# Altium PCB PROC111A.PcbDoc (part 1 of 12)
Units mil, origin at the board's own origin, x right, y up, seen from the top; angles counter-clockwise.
Board outline 7700 x 2300 mil, 6 copper layers (Top Layer, GND 1, SIG 1, SIG 2, GND 2, Bottom Layer), stack 61.062 mil thick; 841 components, 632 nets, 2914 pads, 1627 vias.
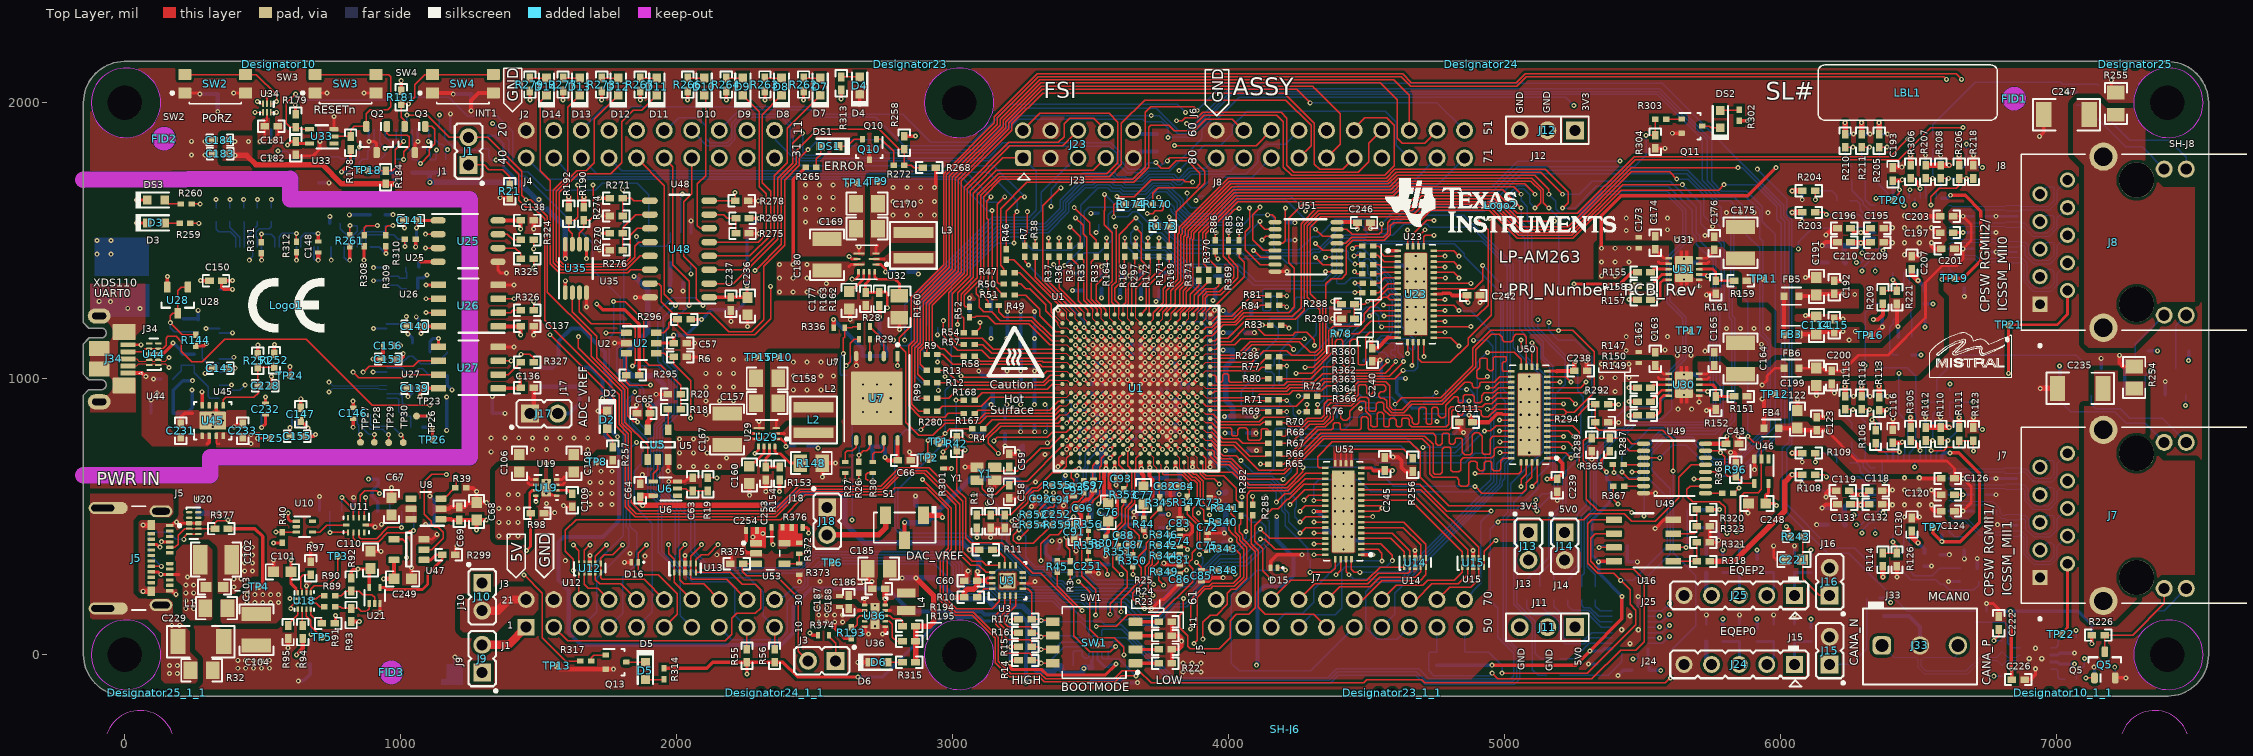
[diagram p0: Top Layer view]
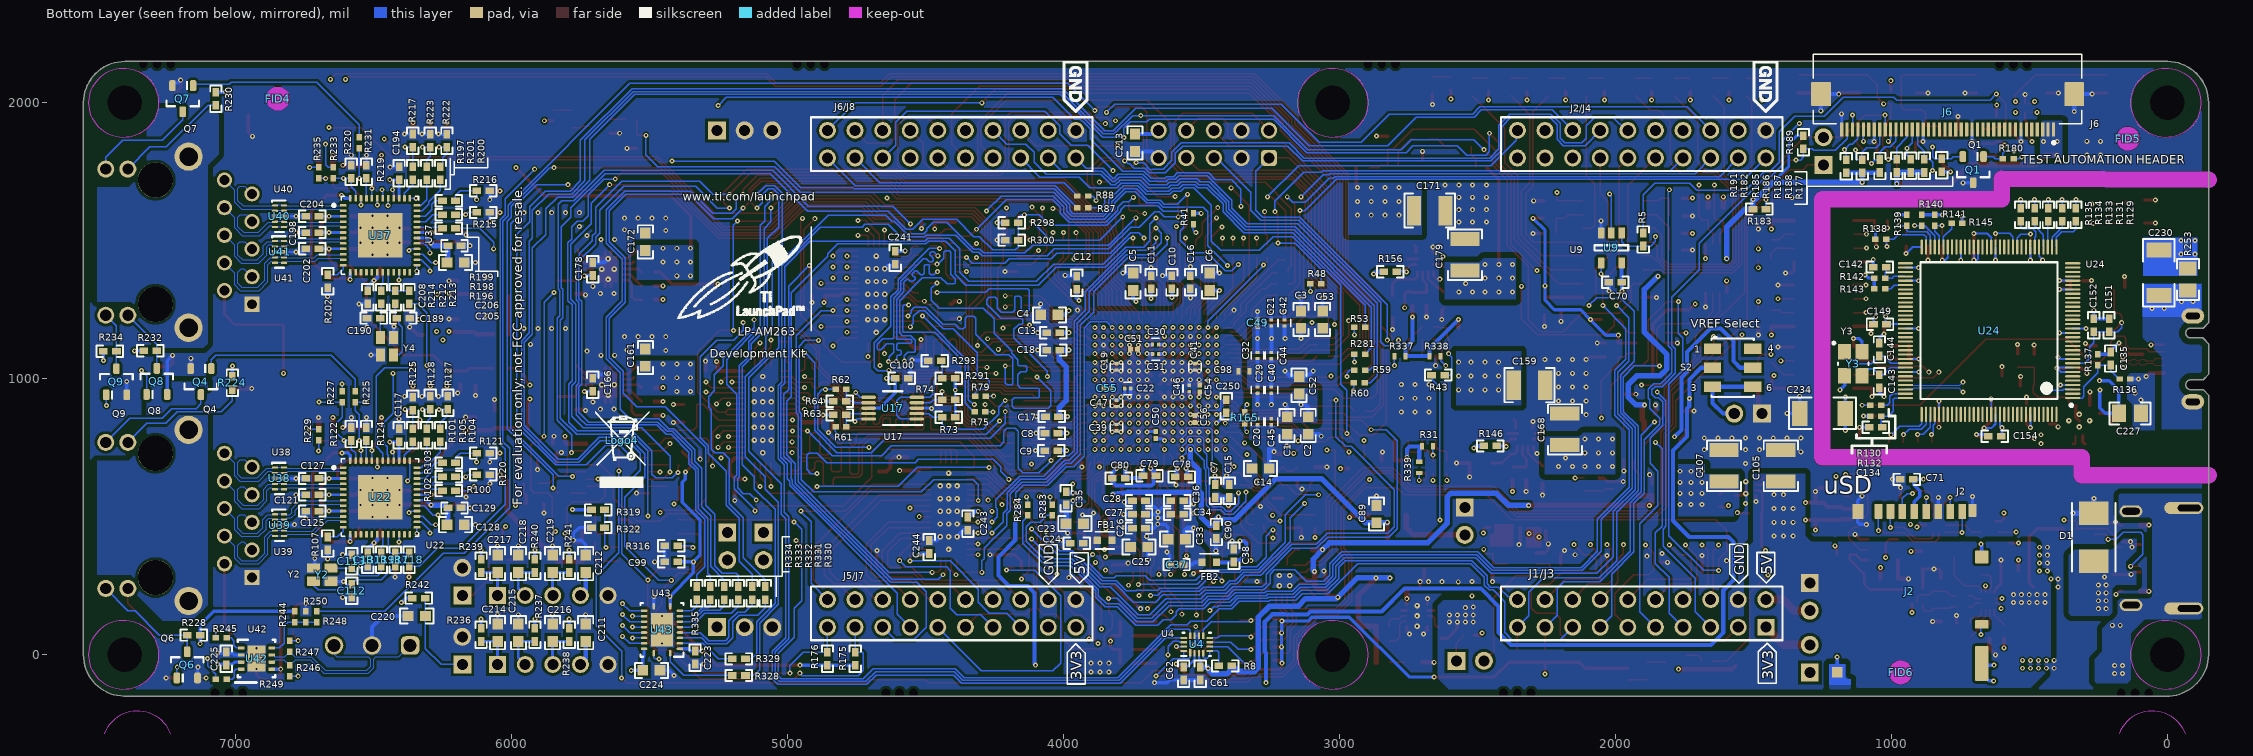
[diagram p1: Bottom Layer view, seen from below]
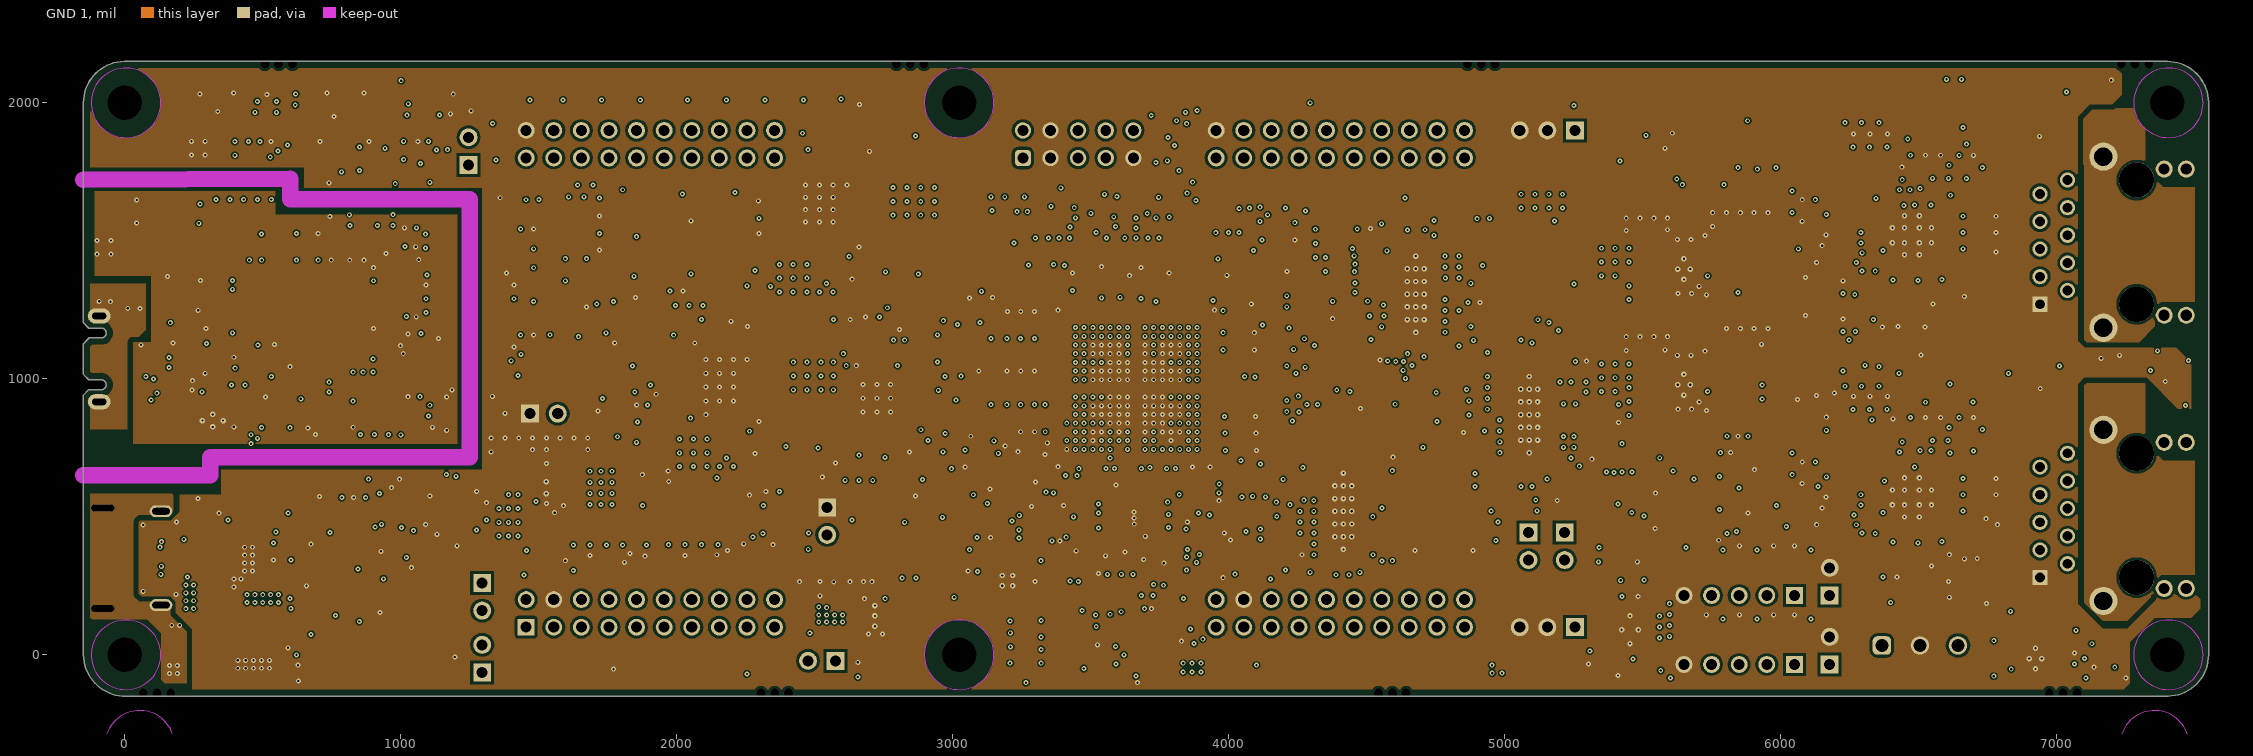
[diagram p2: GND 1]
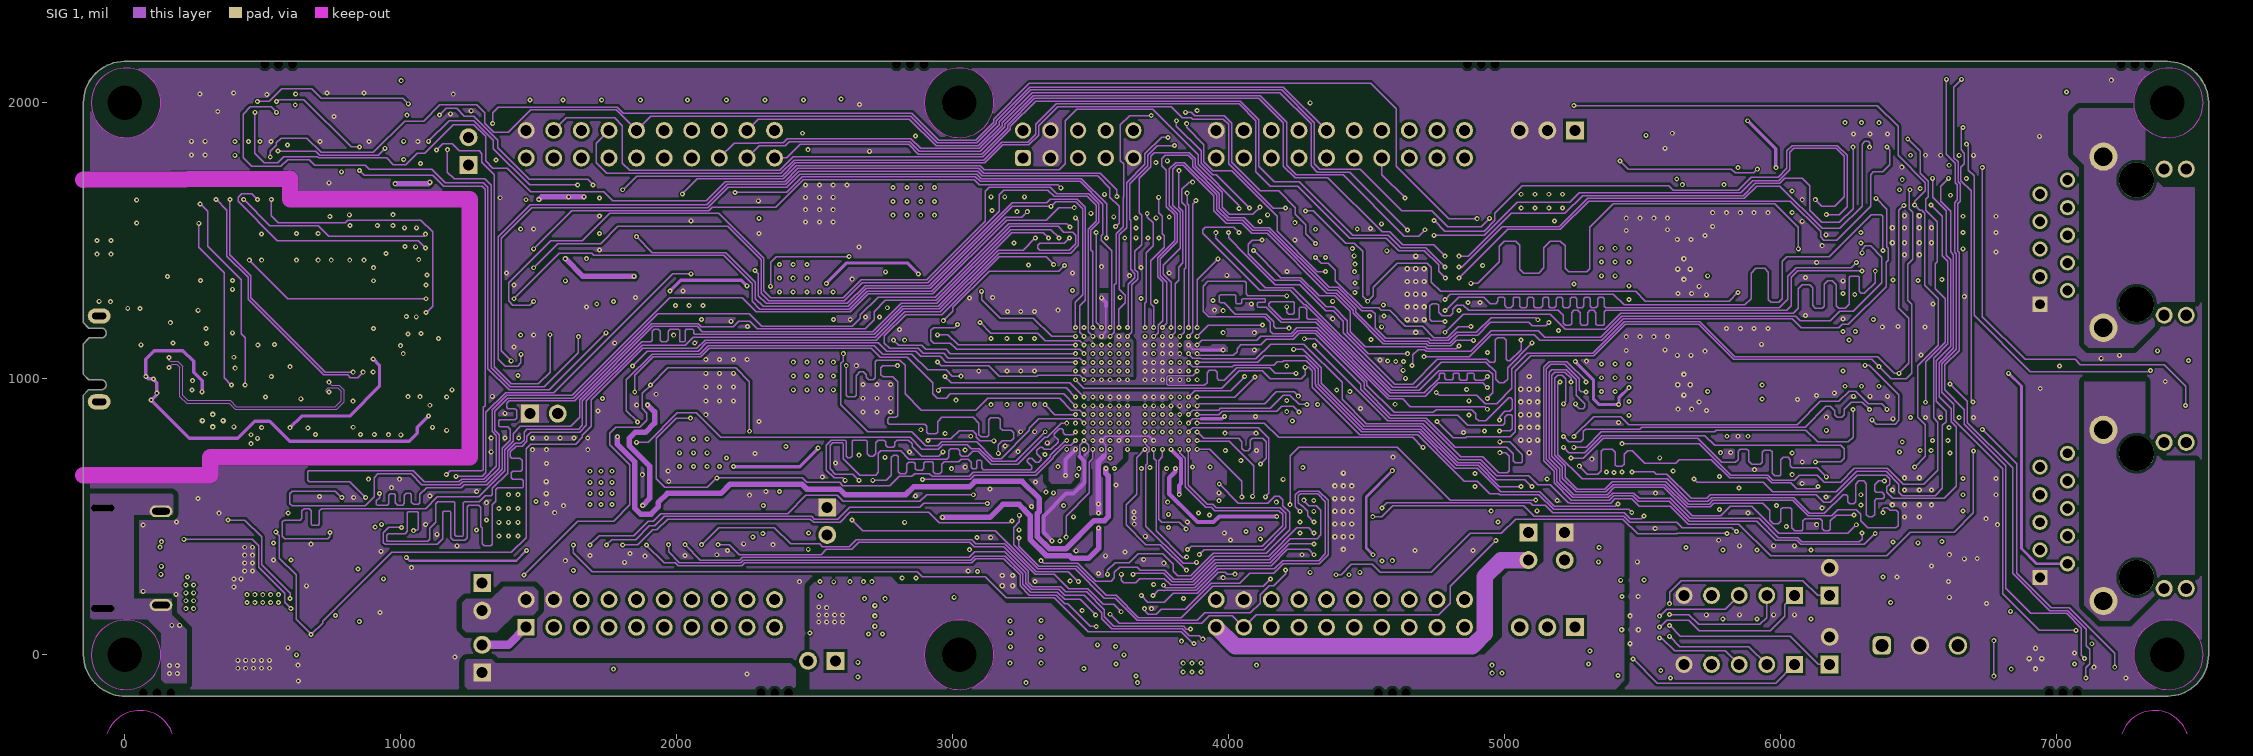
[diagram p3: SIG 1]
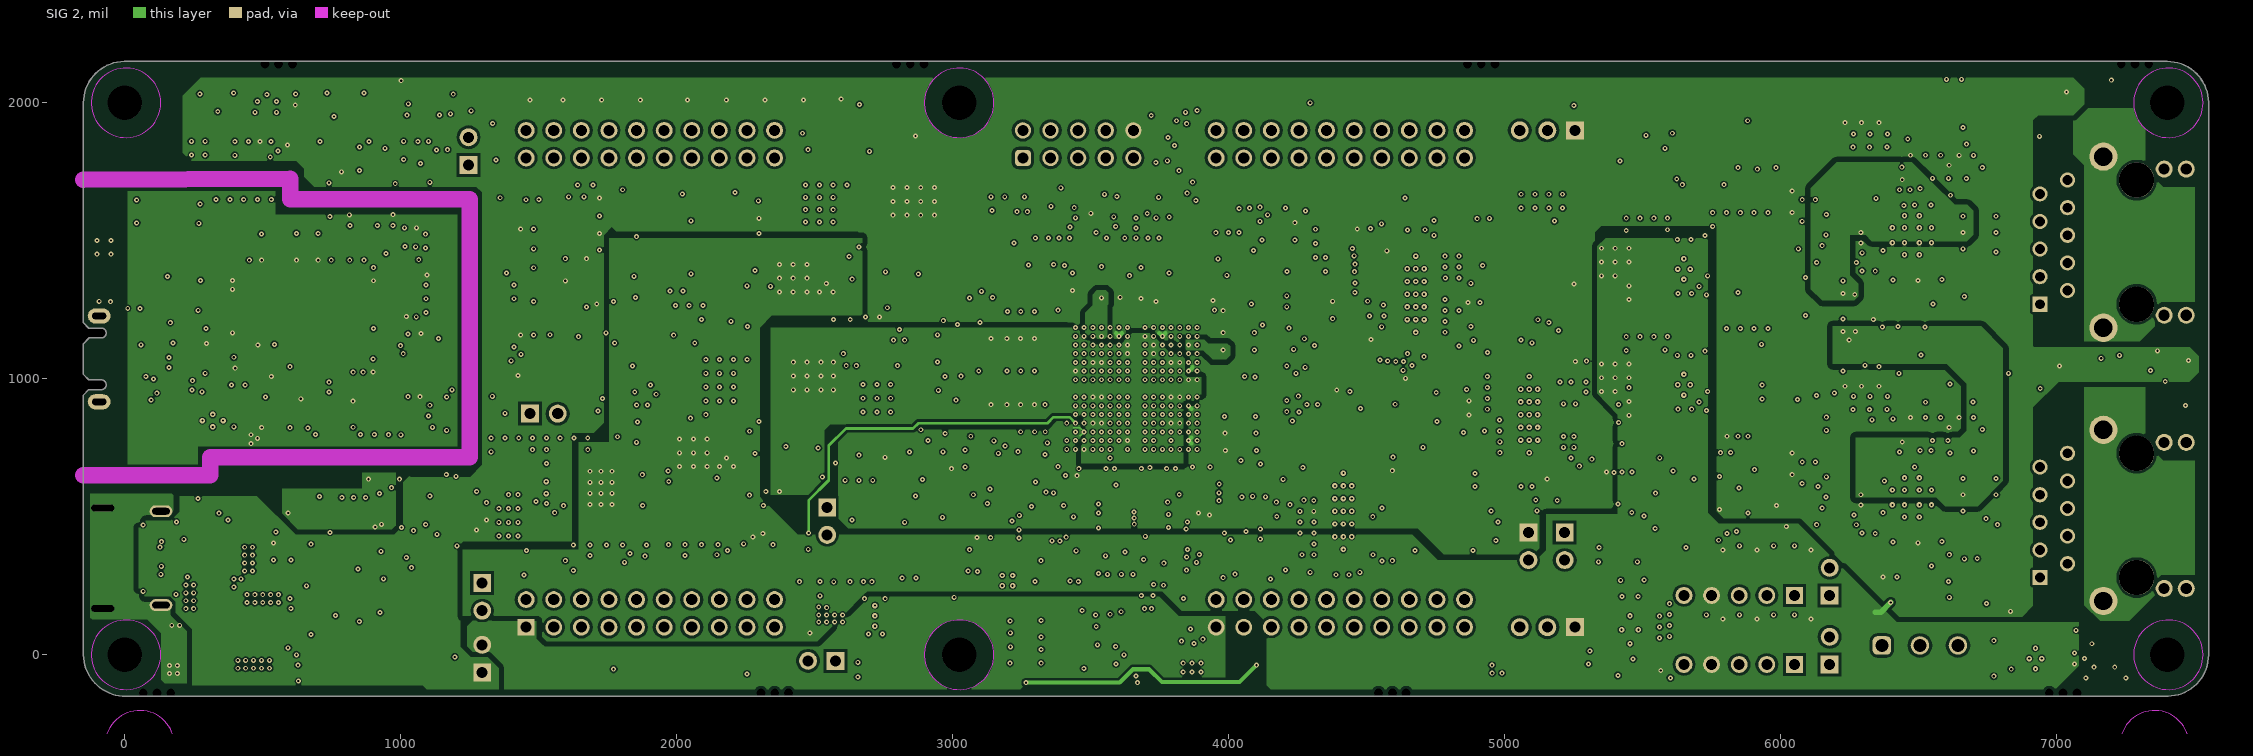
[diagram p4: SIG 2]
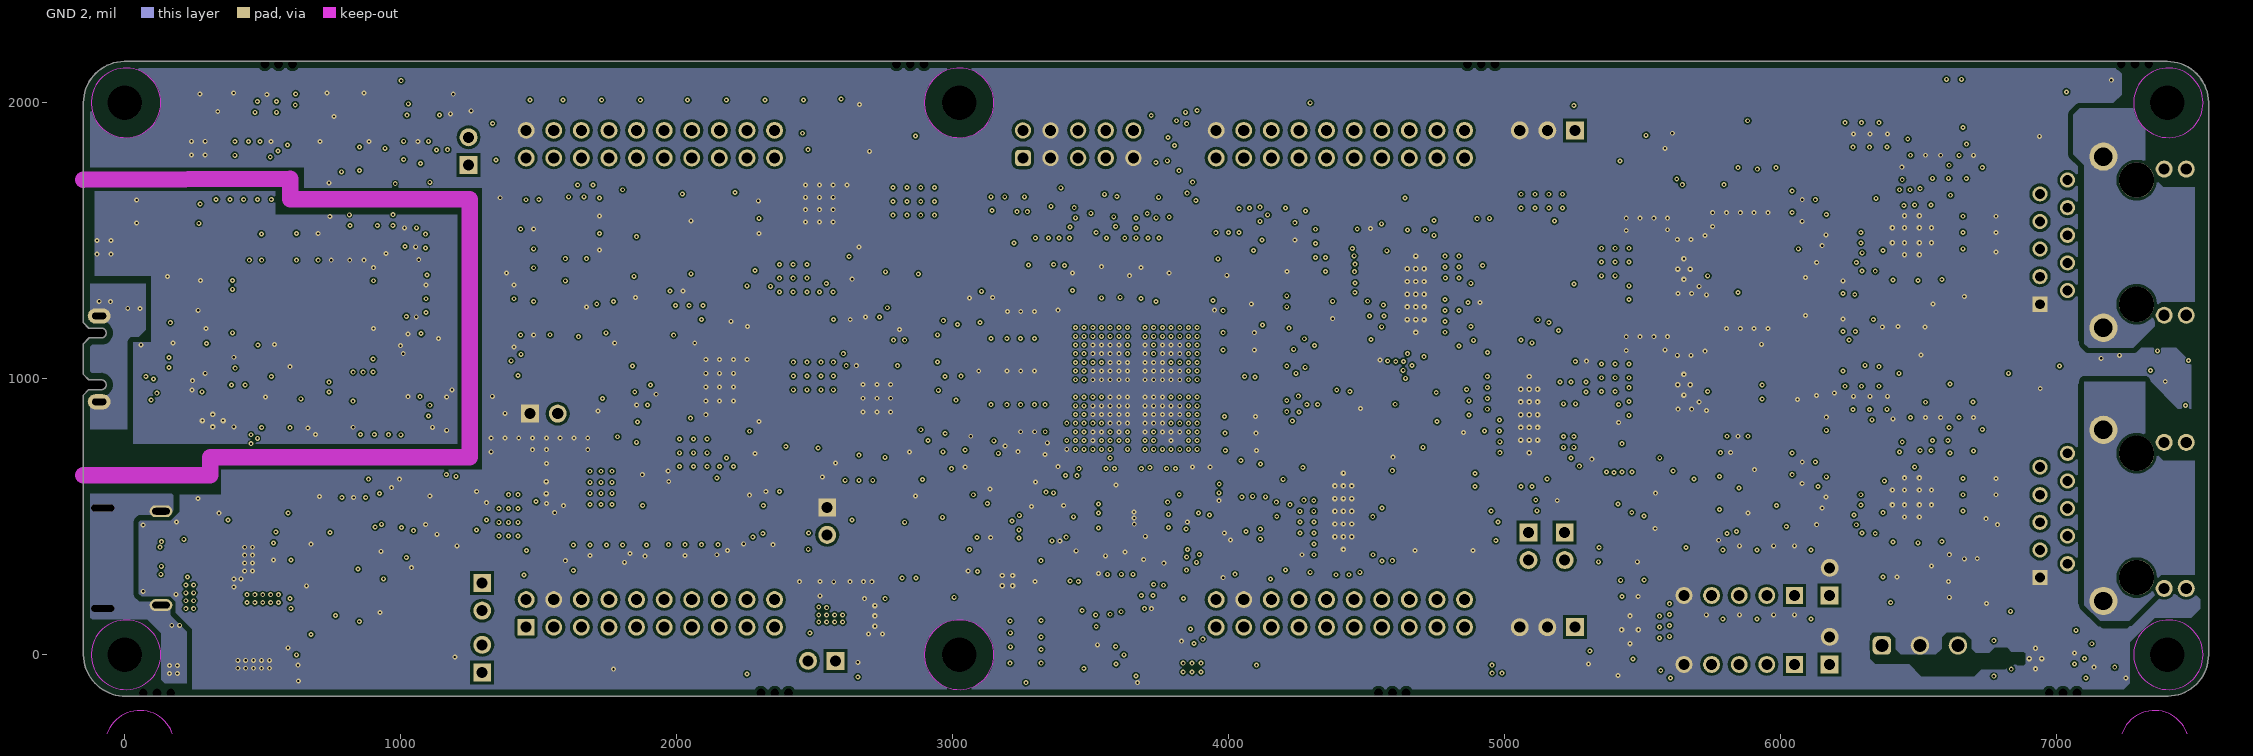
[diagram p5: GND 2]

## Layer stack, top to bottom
Top Solder: solder mask 1, Taiyo PSR 4000 HFX DI-GREEN, Dk 3.5
Top Layer: signal copper 2.087
Dielectric 1: prepreg 3.511, Iteq IT180A Prepreg 2113 RC58, Dk 4.13
GND 1: signal copper 1.26
Dielectric 3: core 4, Iteq IT180A 4 mil core 1/1, Dk 4.4
SIG 1: signal copper 1.26
Dielectric 5: core 1.75, Iteq IT180A Prepreg 106 RC71.5, Dk 3.79
Dielectric 7: core 2.663, Iteq IT180A Prepreg 1080 RC65, Dk 3.86
Dielectric1: core 28, Iteq IT180A 28 mil core H/H, Dk 4.53
Dielectric 8: core 2.663, Iteq IT180A Prepreg 1080 RC65, Dk 3.86
Dielectric 6: core 1.75, Iteq IT180A Prepreg 106 RC71.5, Dk 3.79
SIG 2: signal copper 1.26
Dielectric 4: core 4, Iteq IT180A 4 mil core 1/1, Dk 4.4
GND 2: signal copper 1.26
Dielectric 2: prepreg 3.511, Iteq IT180A Prepreg 2113 RC58, Dk 4.13
Bottom Layer: signal copper 2.087
Bottom Solder: solder mask 1, Taiyo PSR 4000 HFX DI-GREEN, Dk 3.5

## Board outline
-150,0 -150,941.28 -130.32,960.97 -84.25,960.97 ccw(c-84.25,977.87) -67.34,977.87 ccw(c-85.87,977.87) -85.87,996.4 -130.32,996.4 -150,1016.08 -150,1127.3 -130.32,1146.99 -130.32,1147.97 -85.04,1147.97 ccw(c-85.04,1165.67) -67.34,1165.67 -67.34,1166.5 ccw(c-84.25,1166.5) -84.25,1183.41 -130.32,1183.41 -150,1203.09 -150,1278.88 -150,1999.99 cw(c0,2000) -2.06,2149.99 0,2150 7399.99,2150 cw(c7400,2000) 7549.99,2002.06 7550,2000 7550,0.01 cw(c7400,0) 7402.06,-149.99 7400,-149.99 0,-150 4.17,-150 cw(c2.09,2.09)

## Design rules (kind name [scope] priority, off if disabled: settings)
AssemblyTestPointUsage [All] p1: valid=2
BoardOutlineClearance BoardOutlineClearance_MountingHoles [OnCopper and InComponentClass('Mounting Holes')] p1: gap=39.37 ignorepadtopadclearanceinfootprint=FALSE
BoardOutlineClearance BoardOutlineClearance_Poly [OnCopper and IsPoly] p2: gap=25 ignorepadtopadclearanceinfootprint=FALSE
BoardOutlineClearance [OnCopper and Not InComponentClass('Logo') and not InComponentClass('FiducialMark') and not InRegion(1000,500,4000,800) and not InPoly] p3: gap=40 ignorepadtopadclearanceinfootprint=FALSE except(15: SMDPad-OutlineEdge THPad-OutlineEdge; 25: Fill-OutlineEdge)
Clearance Clearance_Keepouts [IsKeepOut] p1: gap=1 ignorepadtopadclearanceinfootprint=FALSE
Clearance proc111 [WithinRoom('PROC111_Hardware')] p2: gap=4 ignorepadtopadclearanceinfootprint=TRUE except(8: Fill-Fill Fill-Poly Fill-Region; 12: Poly-Poly Poly-Region Region-Region)
Clearance 4mil [WithinRoom('SOC_4mil')] p3: gap=4 ignorepadtopadclearanceinfootprint=TRUE except(15: Fill-Fill Fill-Poly Fill-Region Poly-Poly Poly-Region Region-Region)
Clearance ADC_EXT [(OnLayer('Top Layer') or OnLayer('Bottom Layer')) vs InNetClass('ADC0')] p4: gap=7.87 ignorepadtopadclearanceinfootprint=TRUE except(6: Via-Fill Via-Poly Via-Region; 10.6: Arc-Arc Arc-Track Track-Track; 18: Via-Via; 25: Fill-Fill Fill-Poly Fill-Region Poly-Poly Poly-Region Region-Region)
Clearance ADC_SIG1 [OnLayer('SIG 1') vs InNetClass('ADC0')] p5: gap=7.87 ignorepadtopadclearanceinfootprint=TRUE except(6: Via-Fill Via-Poly Via-Region; 9.5: Arc-Arc Arc-Track Track-Track; 18: Via-Via; 25: Fill-Fill Fill-Poly Fill-Region Poly-Poly Poly-Region Region-Region)
Clearance 100E_CLR_same [InDifferentialPairClass('100E')] p6: gap=7.87 ignorepadtopadclearanceinfootprint=TRUE except(7.7: Arc-Arc Arc-Track Track-Track; 10: Via-Fill Via-Poly Via-Region; 18: Via-Via; 25: Fill-Fill Fill-Poly Fill-Region Poly-Poly Poly-Region Region-Region)
Clearance 100E_CLR [InDifferentialPairClass('100E')] p7: gap=7.87 ignorepadtopadclearanceinfootprint=TRUE except(6: Via-Fill Via-Poly Via-Region; 16.2: Arc-Arc Arc-Track Track-Track; 18: Via-Via; 25: Fill-Fill Fill-Poly Fill-Region Poly-Poly Poly-Region Region-Region)
Clearance Clearance_Poly [InPolygon] p8: gap=10 ignorepadtopadclearanceinfootprint=TRUE except(4: Via-Fill Via-Poly Via-Region; 20: Fill-Fill Fill-Poly Fill-Region Poly-Poly Poly-Region Region-Region)
Clearance DIff_spacing [All vs InDifferentialPair('XDSET_1_D')] p9: gap=7.87 ignorepadtopadclearanceinfootprint=TRUE except(5: Arc-Arc Arc-Track Track-Track; 6: Via-Fill Via-Poly Via-Region; 18: Via-Via; 25: Fill-Fill Fill-Poly Fill-Region Poly-Poly Poly-Region Region-Region)
Clearance [All] p10: gap=7.87 ignorepadtopadclearanceinfootprint=TRUE except(5.3: Arc-Arc Arc-Track Track-Track; 6: SMDPad-SMDPad Via-Fill Via-Poly Via-Region; 7: Via-Via; 7.4: Arc-SMDPad Track-SMDPad; 7.5: SMDPad-Via; 25: Fill-Fill Fill-Poly Fill-Region Poly-Poly Poly-Region Region-Region)
ComponentClearance ComponentClearance_EXCEPTION [HasFootprint('0402_070*')or HasFootprint('0402*')] p1: gap=8 collisioncheckmode=3 verticalgap=8 showdistances=FALSE
ComponentClearance ComponentClearance_MountingHoles_FiducialMarks [InComponentClass('Mounting Holes') vs InComponentClass('FiducialMark')] p2: gap=50 collisioncheckmode=3 verticalgap=10 showdistances=FALSE
ComponentClearance ComponentClearance_Shunt [InComponentClass('Header') vs InComponentClass('Shunt')] p3: gap=0 collisioncheckmode=3 verticalgap=0 showdistances=FALSE
ComponentClearance ComponentClearance_Logo [InComponentClass('Logo')] p4: gap=30 collisioncheckmode=3 verticalgap=10 showdistances=FALSE
ComponentClearance ComponentClearance_ScrewToNut [(HasFootprint('NY PMS 440 0025 PH')) vs (HasFootprint('Keystone_1902C'))] p5: gap=5 collisioncheckmode=3 verticalgap=10 showdistances=FALSE
ComponentClearance ComponentClearance_MountingHoles [InComponentClass('Mounting Holes')] p6: gap=100 collisioncheckmode=3 verticalgap=100000 showdistances=FALSE
ComponentClearance ComponentClearance_SmallPassives [HasFootprint('0201*') or HasFootprint('0508') or HasFootprint('0603*') or HasFootprint('0612') or HasFootprint('0805*') or HasFootprint('0815*') or HasFootprint('0830*') or HasFootprint('1206*') or HasFootprint('1210*') or HasFootprint('1808*') or HasFootprint('1812*') or HasFootprint('1825*') or HasFootprint('2010*') or HasFootprint('2220*') or HasFootprint('2225*') or HasFootprint('2512*') or HasFootprint('2728*') or HasFootprint('3518*') vs HasFootprint('0201*') or HasFootprint('0402*') or HasFootprint('0508') or HasFootprint('0603*') or HasFootprint('0612') or HasFootprint('0805*') or HasFootprint('0815*') or HasFootprint('0830*') or HasFootprint('1206*') or HasFootprint('1210*') or HasFootprint('1808*') or HasFootprint('1812*') or HasFootprint('1825*') or HasFootprint('2010*') or HasFootprint('2220*') or HasFootprint('2225*') or HasFootprint('2512*') or HasFootprint('2728*') or HasFootprint('3518*')] p7: gap=10 collisioncheckmode=3 verticalgap=10 showdistances=FALSE
ComponentClearance ComponentClearance_THtoSMT [IsThruComponent vs IsSMTComponent] p8: gap=30 collisioncheckmode=3 verticalgap=30 showdistances=FALSE
ComponentClearance ComponentClearance_THtoTH [IsThruComponent vs IsThruComponent] p9: gap=20 collisioncheckmode=3 verticalgap=30 showdistances=FALSE
ComponentClearance [All] p10: gap=15 collisioncheckmode=3 verticalgap=15 showdistances=TRUE
DiffPairsRouting 90E [InDifferentialPair('XDSET_1_D')] p1: maxlimit=10 minlimit=5 mostfreqgap=10 toplayer_prefgap=5 toplayer_minwidth=4.2 toplayer_maxwidth=15 toplayer_prefwidth=4.2 midlayer1_mingap=6 midlayer1_maxgap=6 midlayer1_prefgap=6 midlayer1_minwidth=4 midlayer1_maxwidth=4 midlayer1_prefwidth=4 midlayer2_mingap=10 midlayer2_minwidth=15 midlayer2_maxwidth=15 midlayer2_prefwidth=15 midlayer3_mingap=10 midlayer3_minwidth=15 midlayer3_maxwidth=15 midlayer3_prefwidth=15 midlayer4_mingap=10 midlayer4_minwidth=15 midlayer4_maxwidth=15 midlayer4_prefwidth=15 bottomlayer_prefgap=5 bottomlayer_minwidth=4.2 bottomlayer_maxwidth=15 bottomlayer_prefwidth=4.2 maxuncoupledlength=500
DiffPairsRouting 120E [InDifferentialPair('CANA')] p2: maxlimit=10 minlimit=6.8 mostfreqgap=10 toplayer_prefgap=6.8 toplayer_minwidth=4.1 toplayer_maxwidth=15 toplayer_prefwidth=4.1 midlayer1_mingap=10 midlayer1_minwidth=15 midlayer1_maxwidth=15 midlayer1_prefwidth=15 midlayer2_mingap=10 midlayer2_minwidth=15 midlayer2_maxwidth=15 midlayer2_prefwidth=15 midlayer3_mingap=10 midlayer3_minwidth=15 midlayer3_maxwidth=15 midlayer3_prefwidth=15 midlayer4_mingap=10 midlayer4_minwidth=15 midlayer4_maxwidth=15 midlayer4_prefwidth=15 bottomlayer_prefgap=6.8 bottomlayer_minwidth=4.1 bottomlayer_maxwidth=15 bottomlayer_prefwidth=4.1 maxuncoupledlength=500
DiffPairsRouting 100E_DIFF [InDifferentialPairClass('100E')] p3: maxlimit=100 minlimit=7.7 mostfreqgap=10 toplayer_maxgap=7.7 toplayer_prefgap=7.7 toplayer_minwidth=4 toplayer_maxwidth=4 toplayer_prefwidth=4 midlayer1_mingap=8.1 midlayer1_maxgap=8.1 midlayer1_prefgap=8.1 midlayer1_minwidth=3.5 midlayer1_maxwidth=3.5 midlayer1_prefwidth=3.5 midlayer2_mingap=10 midlayer2_minwidth=15 midlayer2_maxwidth=15 midlayer2_prefwidth=15 midlayer3_mingap=10 midlayer3_minwidth=15 midlayer3_maxwidth=15 midlayer3_prefwidth=15 midlayer4_mingap=10 midlayer4_minwidth=15 midlayer4_maxwidth=15 midlayer4_prefwidth=15 bottomlayer_maxgap=7.7 bottomlayer_prefgap=7.7 bottomlayer_minwidth=4 bottomlayer_maxwidth=4 bottomlayer_prefwidth=4 maxuncoupledlength=1000
FabricationTestPointUsage TestPointUsage [All] p1: valid=2 allowmultiple=FALSE
FabricationTestpoint Testpoint [All] p1: side=3 testpointundercomponent=TRUE minsize=40 maxsize=100 preferedsize=60 minholesize=0 maxholesize=40 preferedholesize=32 testpointgrid=1 allowsidetop=TRUE allowsidebottom=TRUE usegrid=TRUE gridtolerance=0.01
FanoutControl Fanout_LCC [IsLCC] p1: bgadir=Out bgaviamode=Centered fanoutstyle=Auto fanoutdirection=Alternating viagrid=1 // Fanout_LCC (Default Rule)
FanoutControl Fanout_BGA [IsBGA] p2: bgadir=Out bgaviamode=Centered fanoutstyle=Auto fanoutdirection=Alternating viagrid=1 // Fanout_BGA (Default Rule)
FanoutControl Fanout_Default [All] p4: bgadir=Out bgaviamode=Centered fanoutstyle=Auto fanoutdirection=Alternating viagrid=1 // Fanout_Default (Default Rule)
FanoutControl Fanout_Small [(CompPinCount < 5)] p5: bgadir=Out bgaviamode=Centered fanoutstyle=Auto fanoutdirection=OutThenIn viagrid=1 // Fanout_Small (Default Rule)
HoleSize [All] p1: absolutevalues=TRUE maxlimit=251 minlimit=7.87 maxpercent=80.000 minpercent=20.000
MatchedLengths DIFF [All] p1: tolerance=2 checknetsindiffpair=TRUE checkdiffpairvsdiffpair=FALSE checkxsignals=FALSE checkothers=FALSE
MatchedLengths QSPI [InxSignalClass('QSPI_FLASH')] p2: tolerance=25 checknetsindiffpair=FALSE checkdiffpairvsdiffpair=TRUE checkxsignals=TRUE checkothers=TRUE
MatchedLengths ETH1_RX [InxSignalClass('ETH1_RX')] p3: tolerance=7.5 checknetsindiffpair=FALSE checkdiffpairvsdiffpair=TRUE checkxsignals=TRUE checkothers=TRUE
MatchedLengths ETH1_TX [InxSignalClass('ETH1_TX')] p4: tolerance=7.5 checknetsindiffpair=FALSE checkdiffpairvsdiffpair=TRUE checkxsignals=TRUE checkothers=TRUE
MatchedLengths ICSSM_MII0_RX [InxSignalClass('ICSSM_MII0_RX')] p5: tolerance=7.5 checknetsindiffpair=FALSE checkdiffpairvsdiffpair=TRUE checkxsignals=TRUE checkothers=TRUE
MatchedLengths AM263_RGMII1_TX [InxSignalClass('AM263_RGMII1_TX')] p6: tolerance=7.5 checknetsindiffpair=FALSE checkdiffpairvsdiffpair=TRUE checkxsignals=TRUE checkothers=TRUE
MatchedLengths PRO_PROU_GPIO(0-6) [InxSignalClass('PRO_PROU_GPIO(0-6)')] p7: tolerance=7.5 checknetsindiffpair=FALSE checkdiffpairvsdiffpair=TRUE checkxsignals=TRUE checkothers=TRUE
MatchedLengths PRO_PROU_GPIO(11-16) [InxSignalClass('PRO_PROU_GPIO(11-16)')] p8: tolerance=7.5 checknetsindiffpair=FALSE checkdiffpairvsdiffpair=TRUE checkxsignals=TRUE checkothers=TRUE
MatchedLengths AM263_RGMII1_RX [InxSignalClass('AM263_RGMII1_RX')] p9: tolerance=7.5 checknetsindiffpair=FALSE checkdiffpairvsdiffpair=TRUE checkxsignals=TRUE checkothers=TRUE
MatchedLengths ICSSM_MII0_TX [InxSignalClass('ICSSM_MII0_TX')] p10: tolerance=7.5 checknetsindiffpair=FALSE checkdiffpairvsdiffpair=TRUE checkxsignals=TRUE checkothers=TRUE
MatchedLengths ICSSM_MII1_TX [InxSignalClass('ICSSM_MII1_TX')] p11: tolerance=7.5 checknetsindiffpair=FALSE checkdiffpairvsdiffpair=TRUE checkxsignals=TRUE checkothers=TRUE
MatchedLengths ICSSM_MII1_RX [InxSignalClass('ICSSM_MII1_RX')] p12: tolerance=7.5 checknetsindiffpair=FALSE checkdiffpairvsdiffpair=TRUE checkxsignals=TRUE checkothers=TRUE
MatchedLengths "SD CARD" [InxSignalClass('MMC0')] p13: tolerance=25 checknetsindiffpair=FALSE checkdiffpairvsdiffpair=TRUE checkxsignals=TRUE checkothers=TRUE
MinimumAnnularRing MinimumAnnularRing_ThermalPadVias [IsVia and InAnyComponent] p1: minimumring=5.91
MinimumAnnularRing [All] p2: minimumring=5
MinimumSolderMaskSliver MinimumSolderMaskSliver_Logo [InComponentClass('Logo') vs InComponentClass('Logo')] p1: minsoldermaskwidth=0.7
PlaneConnect [All] p1: planeconnectstyle=Direct reliefexpansion=10 reliefentries=4 reliefconductorwidth=10 reliefairgap=10
PolygonConnect PolygonConnect_3 [All vs IsNamedPolygon('SIG 2-vusb_3v3')] p1: connectstyle=Direct reliefconductorwidth=10 reliefentries=4 polygonreliefangle="90 Angle" airgapwidth=10
PolygonConnect PolygonConnect_2 [All vs IsNamedPolygon('Top Layer-VBUS_TYPEC_5V0')] p2: connectstyle=Direct reliefconductorwidth=10 reliefentries=4 polygonreliefangle="90 Angle" airgapwidth=10
PolygonConnect PolygonConnect_1 [All vs IsNamedPolygon('Top Layer-VBUS_TYPEC_5V0')] p3: connectstyle=Direct reliefconductorwidth=10 reliefentries=4 polygonreliefangle="90 Angle" airgapwidth=10
PolygonConnect [All] p4: connectstyle=Direct reliefconductorwidth=10 reliefentries=4 polygonreliefangle="90 Angle" airgapwidth=10
RoomDefinition PROC111_AM263x_1_Power [InComponentClass('PROC111_AM263x_1_Power')] p1: confinementstyle=ConfineIn formatcopy=TRUE lockcomponents=FALSE outline -842,-1684 1158,-1684 1158,-684 -842,-684
RoomDefinition PROC111_AM263x_8_SDFM [InComponentClass('PROC111_AM263x_8_SDFM')] p2: confinementstyle=ConfineIn formatcopy=TRUE lockcomponents=FALSE outline 7608,966 8433,966 8433,1166 7608,1166
RoomDefinition PROC111_XDS110_2 [InComponentClass('PROC111_XDS110_2')] p3: confinementstyle=ConfineIn formatcopy=TRUE lockcomponents=FALSE outline -842,-1684 1158,-1684 1158,-684 -842,-684
RoomDefinition PROC111_XDS110_1 [InComponentClass('PROC111_XDS110_1')] p4: confinementstyle=ConfineIn formatcopy=TRUE lockcomponents=FALSE outline -842,-1684 1158,-1684 1158,-684 -842,-684
RoomDefinition PROC111_Test_Automation [InComponentClass('PROC111_Test_Automation')] p5: confinementstyle=ConfineIn formatcopy=TRUE lockcomponents=FALSE outline -842,-1684 1158,-1684 1158,-684 -842,-684
RoomDefinition PROC111_System_Power_2 [InComponentClass('PROC111_System_Power_2')] p6: confinementstyle=ConfineIn formatcopy=TRUE lockcomponents=FALSE outline -842,-1684 1158,-1684 1158,-684 -842,-684
RoomDefinition PROC111_System_Power_1 [InComponentClass('PROC111_System_Power_1')] p7: confinementstyle=ConfineIn formatcopy=TRUE lockcomponents=FALSE outline -842,-1684 1158,-1684 1158,-684 -842,-684
RoomDefinition PROC111_Push_Buttons [InComponentClass('PROC111_Push_Buttons')] p8: confinementstyle=ConfineIn formatcopy=TRUE lockcomponents=FALSE outline -842,-1684 1158,-1684 1158,-684 -842,-684
RoomDefinition PROC111_LED [InComponentClass('PROC111_LED')] p9: confinementstyle=ConfineIn formatcopy=TRUE lockcomponents=FALSE outline -842,-1684 1158,-1684 1158,-684 -842,-684
RoomDefinition PROC111_Ehernet_RJ45_2 [InComponentClass('PROC111_Ehernet_RJ45_2')] p10: confinementstyle=ConfineIn formatcopy=TRUE lockcomponents=FALSE outline -842,-1684 1158,-1684 1158,-684 -842,-684
RoomDefinition PROC111_Ehernet_RJ45_1 [InComponentClass('PROC111_Ehernet_RJ45_1')] p11: confinementstyle=ConfineIn formatcopy=TRUE lockcomponents=FALSE outline -842,-1684 1158,-1684 1158,-684 -842,-684
RoomDefinition PROC111_Ehernet_PHY_2 [InComponentClass('PROC111_Ehernet_PHY_2')] p12: confinementstyle=ConfineIn formatcopy=TRUE lockcomponents=FALSE outline -842,-1684 1158,-1684 1158,-684 -842,-684
RoomDefinition PROC111_Ehernet_PHY_1 [InComponentClass('PROC111_Ehernet_PHY_1')] p13: confinementstyle=ConfineIn formatcopy=TRUE lockcomponents=FALSE outline -842,-1684 1158,-1684 1158,-684 -842,-684
RoomDefinition PROC111_Breakout_Headers [InComponentClass('PROC111_Breakout_Headers')] p14: confinementstyle=ConfineIn formatcopy=TRUE lockcomponents=FALSE outline -842,-1684 1158,-1684 1158,-684 -842,-684
RoomDefinition PROC111_Boosterpack_Headers [InComponentClass('PROC111_Boosterpack_Headers')] p15: confinementstyle=ConfineIn formatcopy=TRUE lockcomponents=FALSE outline -842,-1684 1158,-1684 1158,-684 -842,-684
RoomDefinition PROC111_AM263x_Serial_Connectivity [InComponentClass('PROC111_AM263x_Serial_Connectivity')] p16: confinementstyle=ConfineIn formatcopy=TRUE lockcomponents=FALSE outline -842,-1684 1158,-1684 1158,-684 -842,-684
RoomDefinition PROC111_AM263x_7_PRU [InComponentClass('PROC111_AM263x_7_PRU')] p17: confinementstyle=ConfineIn formatcopy=TRUE lockcomponents=FALSE outline -842,-1684 1158,-1684 1158,-684 -842,-684
RoomDefinition PROC111_AM263x_6_RGMII_MII [InComponentClass('PROC111_AM263x_6_RGMII_MII')] p18: confinementstyle=ConfineIn formatcopy=TRUE lockcomponents=FALSE outline -842,-1684 1158,-1684 1158,-684 -842,-684
RoomDefinition PROC111_AM263x_5_ePWM_eQEP_FSI [InComponentClass('PROC111_AM263x_5_ePWM_eQEP_FSI')] p19: confinementstyle=ConfineIn formatcopy=TRUE lockcomponents=FALSE outline -842,-1684 1158,-1684 1158,-684 -842,-684
RoomDefinition PROC111_AM263x_4_ADC_DAC [InComponentClass('PROC111_AM263x_4_ADC_DAC')] p20: confinementstyle=ConfineIn formatcopy=TRUE lockcomponents=FALSE outline -842,-1684 1158,-1684 1158,-684 -842,-684
RoomDefinition PROC111_AM263x_3_QSPI_MMC [InComponentClass('PROC111_AM263x_3_QSPI_MMC')] p21: confinementstyle=ConfineIn formatcopy=TRUE lockcomponents=FALSE outline -842,-1684 1158,-1684 1158,-684 -842,-684
RoomDefinition PROC111_AM263x_2_Clock_Reset_Boot_JTAG [InComponentClass('PROC111_AM263x_2_Clock_Reset_Boot_JTAG')] p22: confinementstyle=ConfineIn formatcopy=TRUE lockcomponents=FALSE outline -842,-1684 1158,-1684 1158,-684 -842,-684
RoomDefinition PROC111_Hardware [InComponentClass('PROC111_Hardware')] p23: confinementstyle=ConfineIn formatcopy=TRUE lockcomponents=FALSE outline 3365.64,665.87 3964.06,665.87 3964.06,1264.29 3365.64,1264.29
RoutingLayers [All] p1: top layer_v5=TRUE mid layer 1_v5=TRUE mid layer 2_v5=TRUE mid layer 3_v5=FALSE mid layer 4_v5=TRUE bottom layer_v5=TRUE
RoutingVias ThermalPadVias [IsVia and InAnyComponent] p1: holewidth=7.87 width=19.68 viastyle="Through Hole" minholewidth=7.87 minwidth=19.68 maxholewidth=12.99 maxwidth=23.62
RoutingVias [All] p2: holewidth=8 width=18 viastyle="Through Hole" minholewidth=8 minwidth=18 maxholewidth=8 maxwidth=18
SilkToBoardRegionClearance [Not ((IsComment or IsDesignator) And (Hide <> 'False')) and not InRegion(1000,500,4000,800)] p1:
SilkToSilkClearance SilkToSilkClearance_Pb-FreeLogo [(HasFootprint('Pb-Free_Overlay_Medium') OR HasFootprint('Pb-Free_Overlay_Small')) vs (HasFootprint('Pb-Free_Overlay_Medium') OR HasFootprint('Pb-Free_Overlay_Small'))] p1: silktosilkclearance=0
SilkToSilkClearance [All] p2: silktosilkclearance=3.94
SilkToSolderMaskClearance SilkToComponentPadClearance [(IsPad or IsFill or IsRegion) and Component] p1: minsilkscreentomaskgap=3.54 clearancetoexposedcopper=TRUE
SilkToSolderMaskClearance "Silk to Solder Mask Opening" [All] p2: minsilkscreentomaskgap=3 clearancetoexposedcopper=FALSE
SolderMaskExpansion [All] p1: expansion=1.97 istentingtop=FALSE
UnRoutedNet [All] p1: checkbadconnections=TRUE
Width 4mil_soc [WithinRoom('SOC_4mil')] p1: maxlimit=20 minlimit=4 preferedwidth=15 toplayer_prefwidth=4 midlayer1_prefwidth=4 midlayer3_minwidth=10 midlayer3_maxwidth=10 midlayer3_prefwidth=10 midlayer4_minwidth=10 midlayer4_maxwidth=10 midlayer4_prefwidth=10 bottomlayer_prefwidth=4 minimp=50.000000 maximp=50.000000 favimp=50.000000
Width "4 mil_mux" [WithinRoom('SOC_4mil_1') or  WithinRoom('SOC_4mil_2') or WithinRoom('SOC_4mil_3')] p2: maxlimit=15 minlimit=4.75 preferedwidth=10 toplayer_minwidth=5.3 toplayer_prefwidth=5.3 midlayer1_maxwidth=10 midlayer1_prefwidth=4.75 midlayer2_maxwidth=10 midlayer3_minwidth=5.3 midlayer3_maxwidth=10 midlayer4_minwidth=5.3 midlayer4_maxwidth=10 bottomlayer_minwidth=5.3 bottomlayer_prefwidth=5.3 minimp=50.000000 maximp=50.000000 favimp=50.000000
Width PWR [InNetClass('PWR')] p3: maxlimit=30 minlimit=6 preferedwidth=12 midlayer1_minwidth=8 midlayer2_minwidth=8 midlayer3_minwidth=8 midlayer4_minwidth=8 bottomlayer_minwidth=7 minimp=50.000000 maximp=50.000000 favimp=50.000000
Width [All] p4: maxlimit=100 minlimit=4 preferedwidth=5.3 midlayer1_minwidth=4.75 midlayer1_prefwidth=4.75 midlayer2_minwidth=5.3 midlayer3_minwidth=5.3 midlayer4_minwidth=5.3 bottomlayer_minwidth=5.3 minimp=50.000000 maximp=50.000000 favimp=50.000000 checkconnectedcopper=TRUE
13 further rules are at their usual default settings.

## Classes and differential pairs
component class PROC111_AM263x_8_SDFM: R369 R370 R371
net class POWER: VBUS_XDS_5V0
component class PROC111_XDS110_2: C134 C135 C136 C137 C138 C139 C140 C141 C142 C143 C144 C145 C146 C147 C148 C149 C150 C151 C152 C153 C154 C155 C156 C234 D3 DS3 R129 R130 R131 R132 R133 R134 R135 R136 R137 R138 R139 R140 R141 R142 R143 R144 R145 R259 R260 R261 R308 R309 R310 R311 R312 R324 R325 R326 R327 TP27 TP28 TP29 TP30 U24 U25 U26 U27 U28 Y3
component class PROC111_XDS110_1: C227 C228 C230 C231 C232 C233 J34 R251 R252 R253 TP23 TP24 TP25 TP26 U44 U45
component class PROC111_Test_Automation: C183 C184 C185 C186 C187 C188 J1 J6 L4 R21 R182 R183 R184 R185 R186 R187 R188 R189 R190 R191 R192 R193 R194 R195 TP18 U35 U36
component class PROC111_System_Power_2: C157 C158 C159 C160 C161 C162 C163 C164 C165 C166 C167 C168 C169 C170 C171 C172 C173 C174 C175 C176 C177 C178 C179 C180 C253 C254 J3 L2 L3 R146 R147 R148 R149 R150 R151 R152 R153 R154 R155 R156 R157 R158 R159 R160 R161 R162 R163 R295 R296 R372 R373 R374 R375 TP8 TP9 TP10 TP11 TP12 TP13 TP14 TP15 TP16 TP17 U29 U30 U31 U32 U53
component class PROC111_System_Power_1: C101 C102 C103 C104 C105 C106 C107 C108 C109 C110 C229 C249 D1 J5 J11 J12 L1 R32 R89 R90 R91 R92 R93 R94 R95 R97 R98 R299 R377 TP3 TP4 TP5 TP6 U18 U19 U20 U21 U47
component class PROC111_Push_Buttons: C181 C182 Q1 Q2 Q3 R177 R178 R179 R180 R181 SW2 SW3 SW4 U33 U34
component class PROC111_LED: C236 C237 D2 D4 D5 D6 D7 D8 D9 D10 D11 D12 D13 D14 DS1 DS2 Q10 Q11 Q13 R257 R262 R263 R264 R265 R266 R267 R268 R269 R270 R271 R272 R273 R274 R275 R276 R277 R278 R279 R302 R303 R304 R313 R314 R315 R317 U48
component class PROC111_Ehernet_RJ45_2: C247 J8 Q7 Q8 Q9 R230 R231 R232 R233 R234 R235 R255 TP22 U40 U41
component class PROC111_Ehernet_RJ45_1: C235 J7 Q4 Q5 Q6 R224 R225 R226 R227 R228 R229 R254 TP21 U38 U39
component class PROC111_Ehernet_PHY_2: C189 C190 C191 C192 C193 C194 C195 C196 C197 C198 C199 C200 C201 C202 C203 C204 C205 C206 C207 C208 C209 C210 FB5 FB6 R196 R197 R198 R199 R200 R201 R202 R203 R204 R205 R206 R207 R208 R209 R210 R211 R212 R213 R214 R215 R216 R217 R218 R219 R220 R221 R222 R223 R306 TP19 TP20 U37 Y4
component class PROC111_Ehernet_PHY_1: C112 C113 C114 C115 C116 C117 C118 C119 C120 C121 C122 C123 C124 C125 C126 C127 C128 C129 C130 C131 C132 C133 C240 C241 C242 FB3 FB4 R100 R101 R102 R103 R104 R105 R106 R107 R108 R109 R110 R111 R112 R113 R114 R115 R116 R117 R118 R119 R120 R121 R122 R123 R124 R125 R126 R127 R128 R291 R292 R293 R294 R305 TP7 U22 U50 Y2
component class PROC111_Breakout_Headers: C211 C212 C213 C214 C215 C216 C217 C218 C219 C220 C221 C222 C223 C224 C225 C226 J15 J16 J17 J18 J23 J24 J25 J33 R236 R237 R238 R239 R240 R241 R242 R243 R244 R245 R246 R247 R248 R249 R250 R328 R329 R330 R331 R332 R333 R334 R335 U42 U43
component class PROC111_Boosterpack_Headers: C243 C244 C245 C246 J1/J3 J2/J4 J5/J7 J6/J8 J9 J10 J13 J14 R256 R298 R300 U51 U52
component class PROC111_AM263x_Serial_Connectivity: R164 R165 R166 R167 R168 R169 R170 R171 R172 R173 R174 R175 R176 R297
component class PROC111_AM263x_7_PRU: C43 C111 C238 C239 C248 R71 R72 R73 R74 R75 R76 R77 R78 R79 R80 R81 R82 R83 R84 R85 R86 R87 R88 R96 R286 R287 R288 R289 R290 R360 R361 R362 R363 R364 R365 R366 R367 R368 U23 U46 U49
component class PROC111_AM263x_6_RGMII_MII: C100 R61 R62 R63 R64 R65 R66 R67 R68 R69 R70 U17
component class PROC111_AM263x_5_ePWM_eQEP_FSI: R9 R12 R13 R46 R47 R48 R49 R50 R51 R52 R53 R54 R55 R56 R57 R58 R59 R60 R99 R280 R281 R282 R283 R284 R285
component class PROC111_AM263x_3_QSPI_MMC: C66 C67 C68 C69 C70 C71 J2 R26 R27 R28 R29 R30 R31 R33 R34 R35 R36 R37 R38 R39 R40 R41 R42 R43 R301 R336 R337 R338 R339 U7 U8 U9 U10 U11
component class PROC111_AM263x_2_Clock_Reset_Boot_JTAG: C57 C58 C59 C60 C61 C62 C63 C64 C65 C99 R4 R5 R6 R7 R8 R10 R11 R14 R15 R16 R17 R18 R19 R20 R22 R23 R24 R25 R258 R316 R318 R319 R320 R321 R322 R323 SW1 TP1 TP2 U2 U3 U4 U5 U6 U16 Y1
component class PROC111_AM263x_1_Power: C1 C2 C3 C4 C5 C6 C7 C8 C9 C10 C11 C12 C13 C14 C15 C16 C17 C18 C19 C20 C21 C22 C23 C24 C25 C26 C27 C28 C29 C30 C31 C32 C33 C34 C35 C36 C37 C38 C39 C40 C41 C42 C44 C45 C46 C47 C48 C49 C50 C51 C52 C53 C54 C55 C56 C98 C250 FB1 FB2 R1 R2 R376
component class PROC111_AM263x_4_ADC_DAC: C72 C73 C74 C75 C76 C77 C78 C79 C80 C81 C82 C83 C84 C85 C86 C87 C88 C89 C90 C91 C92 C93 C94 C95 C96 C97 C251 C252 D15 D16 R3 R44 R45 R307 R340 R341 R342 R343 R344 R345 R346 R347 R348 R349 R350 R351 R352 R353 R354 R355 R356 R357 R358 R359 S1 S2 U1 U12 U13 U14 U15
component class PROC111_Hardware: FID1 FID2 FID3 FID4 FID5 FID6 LBL1 Logo1 Logo2 Logo3 Logo4 SH-J1 SH-J2 SH-J3 SH-J4 SH-J5 SH-J6 SH-J7 SH-J8 ZZ1 ZZ2 ZZ3 ZZ4
differential pair XDSET_1_D: +XDSET_1_D_P -XDSET_1_D_N
differential pair ETH2_TD_D: +ETH2_TD_D_P -ETH2_TD_D_N
differential pair ETH2_TD_C: +ETH2_TD_C_P -ETH2_TD_C_N
differential pair ETH2_TD_B: +ETH2_TD_B_P -ETH2_TD_B_N
differential pair ETH2_TD_A: +ETH2_TD_A_P -ETH2_TD_A_N
differential pair ETH1_TD_D: +ETH1_TD_D_P -ETH1_TD_D_N
differential pair ETH1_TD_C: +ETH1_TD_C_P -ETH1_TD_C_N
differential pair ETH1_TD_B: +ETH1_TD_B_P -ETH1_TD_B_N
differential pair ETH1_TD_A: +ETH1_TD_A_P -ETH1_TD_A_N
differential pair CANA: +CANA_P -CANA_N

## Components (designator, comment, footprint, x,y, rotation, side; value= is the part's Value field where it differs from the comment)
1 "Comment" MHNP_M3_PANHEAD_PHILLIPS#1 54.16,-327.94 r0 top
2 "Comment" MHNP_M3_PANHEAD_PHILLIPS#1 7354.16,-327.94 r180 top
3 "Comment" MHNP_M3_PANHEAD_PHILLIPS#1 7354.16,4992.06 r180 top
4 "Comment" MHNP_M3_PANHEAD_PHILLIPS#1 54.16,4992.06 r0 bottom
C1 "C1608X7S1A335K080AC" 0603 3188.57,830.78 r270 bottom value=3.3uF
C2 "C1608X7S1A335K080AC" 0603 3112.14,830.78 r270 bottom value=3.3uF
C3 "C1608X7S1A335K080AC" 0603 3138.51,1214.76 r90 bottom value=3.3uF
C4 "C1608X7S1A335K080AC" 0603 4050,1231.81 r0 bottom value=3.3uF
C5 "C1608X7S1A335K080AC" 0603 3746.57,1351.5 r90 bottom value=3.3uF
C6 "C1608X7S1A335K080AC" 0603 3469.13,1351.5 r90 bottom value=3.3uF
C7 "GRM155R70J104KA01D" 0402 3448.63,593.75 r270 bottom value=0.1uF
C8 "GRM155R70J104KA01D" 0402 4042.18,802.97 r0 bottom value=0.1uF
C9 "GRM155R70J104KA01D" 0402 4043.67,740 r0 bottom value=0.1uF
C10 "GRM155R70J104KA01D" 0402 3606.08,1349.91 r90 bottom value=0.1uF
C11 "GRM155R70J104KA01D" 0402 3681.66,1349.91 r90 bottom value=0.1uF
C12 "GRM155R70J104KA01D" 0402 3950.67,1348.22 r90 bottom value=0.1uF
C13 "GRM155R70J104KA01D" 0402 4036.18,1167.07 r0 bottom value=0.1uF
C14 "C1608X7S1A335K080AC" 0603 3285,674.72 r180 bottom value=3.3uF
C15 "GRM155R70J104KA01D" 0402 3398.63,593.75 r270 bottom value=0.1uF
C16 "GRM155R70J104KA01D" 0402 3538.87,1349.91 r90 bottom value=0.1uF
C17 "GRM155R70J104KA01D" 0402 4040.85,863.32 r0 bottom value=0.1uF
C18 "GRM155R70J104KA01D" 0402 4036.18,1104.06 r0 bottom value=0.1uF
C19 "GRM033C80J105ME05D" FP-GRM033C80J105ME05D_0201-MFG 3806.58,1043.07 r90 bottom value=1µF
C20 "GRM033C80J105ME05D" FP-GRM033C80J105ME05D_0201-MFG 3295.84,844.56 r90 bottom value=1µF
C21 "GRM033C80J105ME05D" FP-GRM033C80J105ME05D_0201-MFG 3245.84,1202.29 r270 bottom value=1µF
C22 "GRM033C80J105ME05D" FP-GRM033C80J105ME05D_0201-MFG 3766.09,965.08 r0 bottom value=1µF
C23 "C1608X7S1A335K080AC" 0603 3957.94,474.92 r0 bottom value=3.3uF
C24 "GRM155R70J104KA01D" 0402 3950.96,404.26 r0 bottom value=0.1uF
C25 "C1608X7S1A335K080AC" 0603 3725,390.45 r180 bottom value=3.3uF
C26 "GRM155R70J104KA01D" 0402 3725.31,458.97 r180 bottom value=0.1uF
C27 "GRM155R70J104KA01D" 0402 3725.31,508.97 r180 bottom value=0.1uF
C28 "GRM155R70J104KA01D" 0402 3725.31,558.97 r180 bottom value=0.1uF
C29 "GRM033C80J105ME05D" FP-GRM033C80J105ME05D_0201-MFG 3295.84,958.91 r270 bottom value=1µF
C30 "GRM033C80J105ME05D" FP-GRM033C80J105ME05D_0201-MFG 3665,1123.75 r180 bottom value=1µF
C31 "GRM033C80J105ME05D" FP-GRM033C80J105ME05D_0201-MFG 3664.85,1089.57 r180 bottom value=1µF
C32 "GRM033C80J105ME05D" FP-GRM033C80J105ME05D_0201-MFG 3295.84,1084.32 r90 bottom value=1µF
C33 "GRM188Z71A475ME15D" 0603 3588.88,419.08 r0 bottom value=4.7uF
C34 "GRM155R70J104KA01D" 0402 3586.38,508.97 r0 bottom value=0.1uF
C35 "GRM155R70J104KA01D" 0402 3989.44,567.13 r270 bottom value=0.1uF
C36 "GRM155R70J104KA01D" 0402 3586.38,558.97 r0 bottom value=0.1uF
C37 "GRM155R70J104KA01D" 0402 3589.37,326.8 r0 bottom value=0.1uF
C38 "GRM155R70J104KA01D" 0402 3381.39,359.65 r90 bottom value=0.1uF
C39 "GRM033C80J105ME05D" FP-GRM033C80J105ME05D_0201-MFG 3806.58,823 r90 bottom value=1µF
C40 "GRM033C80J105ME05D" FP-GRM033C80J105ME05D_0201-MFG 3245.84,958.91 r270 bottom value=1µF
C41 "GRM033C80J105ME05D" FP-GRM033C80J105ME05D_0201-MFG 3523,1043.07 r90 bottom value=1µF
C42 "GRM033C80J105ME05D" FP-GRM033C80J105ME05D_0201-MFG 3198.24,1202.29 r270 bottom value=1µF
C43 "GRM155R71E104KE14D" 0402 5825,764.8 r180 top value=0.1uF
C44 "GRM033C80J105ME05D" FP-GRM033C80J105ME05D_0201-MFG 3245.84,1084.06 r90 bottom value=1µF
C45 "GRM033C80J105ME05D" FP-GRM033C80J105ME05D_0201-MFG 3245.84,844.56 r90 bottom value=1µF
C46 "GRM033C80J105ME05D" FP-GRM033C80J105ME05D_0201-MFG 3543.17,965.1 r270 bottom value=1µF
C47 "GRM033C80J105ME05D" FP-GRM033C80J105ME05D_0201-MFG 3806.58,910.9 r90 bottom value=1µF
C48 "GRM155R70J104KA01D" 0402 3137.47,483.24 r270 top value=0.1uF
C49 "GRM033Z71C104KE14D" 0201 3295.84,1202.29 r90 bottom value=0.1uF
C50 "GRM033Z71C104KE14D" 0201 3664.85,796.1 r90 bottom value=0.1uF
C51 "GRM033Z71C104KE14D" 0201 3742.96,1107.37 r0 bottom value=0.1uF
C52 "C1608X7S1A335K080AC" 0603 3145,976.61 r90 bottom value=3.3uF
C53 "C1608X7S1A335K080AC" 0603 3060,1214.76 r90 bottom value=3.3uF
C54 "GRM033Z71C104KE14D" 0201 3504.78,965.1 r90 bottom value=0.1uF
C55 "GRM033Z71C104KE14D" 0201 3840,965.08 r180 bottom value=0.1uF
C56 "GRM033Z71C104KE14D" 0201 3523,854.38 r90 bottom value=0.1uF
C57 "GRM155R71E104KE14D" 0402 2012.4,1129.45 r180 top value=0.1uF
C58 "GRM1555C1E120JA01D" 0402 3205,591.21 r270 top value=12pF
C59 "GRM1555C1E120JA01D" 0402 3205,704.33 r90 top value=12pF
C60 "GRM155R71E104KE14D" 0402 3065,268.33 r0 top value=0.1uF
C61 "GRM155R71E104KE14D" 0402 3503.69,-68.03 r90 bottom value=0.1uF
C62 "GRM155R71E104KE14D" 0402 3563.69,-68.03 r90 bottom value=0.1uF
C63 "GRM155R71E103KA01D" 0402 2057.84,617.39 r90 top value=0.01uF
C64 "GRM155R71E104KE14D" 0402 1867.57,596.48 r270 top value=0.1uF
C65 "GRM155R71E104KE14D" 0402 1879.22,874.86 r0 top value=0.1uF
C66 "GRM155R71E104KE14D" 0402 2823.62,704.15 r180 top value=0.1uF
C67 "GRM188Z71C475KE21D" 0603 966.44,537.46 r90 top value=4.7uF
C68 "C1608X7S1A335K080AC" 0603 1274.76,519.66 r90 top value=3.3uF
C69 "GRM155R70J104KA01D" 0402 1212.1,511.79 r90 top value=0.1uF
C70 "GRM155R71E104KE14D" 0402 1999.39,1350 r180 bottom value=0.1uF
C71 "GRM155R71E104KE14D" 0402 943.27,635.45 r180 bottom value=0.1uF
C72 "GRM1555C1E331JA01D" 0402S 3923.15,461.57 r90 top value=330pF
C73 "GRM1555C1E331JA01D" 0402S 3931.07,551.48 r270 top value=330pF
C74 "GRM1555C1E331JA01D" 0402S 3822.33,411.86 r270 top value=330pF
C75 "GRM1555C1E331JA01D" 0402S 3922.62,395.63 r270 top value=330pF
C76 "GRM188Z71A475ME15D" 0603 3563.17,516.5 r270 top value=4.7uF
C77 "GRM188Z71A475ME15D" 0603 3691,577.37 r270 top value=4.7uF
C78 "GRM155R70J104KA01D" 0402 3570.36,644.44 r0 bottom value=0.1uF
C79 "GRM155R70J104KA01D" 0402 3687.3,649.09 r0 bottom value=0.1uF
C80 "GRM155R70J104KA01D" 0402 3798.62,639.94 r180 bottom value=0.1uF
C81 "GRM1555C1E331JA01D" 0402S 3822.09,344.5 r90 top value=330pF
C82 "GRM1555C1E331JA01D" 0402S 3768.34,611.49 r180 top value=330pF
C83 "GRM1555C1E331JA01D" 0402S 3822.33,476.02 r270 top value=330pF
C84 "GRM1555C1E331JA01D" 0402S 3836.76,609.98 r0 top value=330pF
C85 "GRM1555C1E331JA01D" 0402S 3901.07,286.72 r90 top value=330pF
C86 "GRM1555C1E331JA01D" 0402S 3822.09,274.13 r90 top value=330pF
C87 "GRM1555C1E331JA01D" 0402S 3655.6,398.92 r0 top value=330pF
C88 "GRM1555C1E331JA01D" 0402S 3618.81,432.5 r180 top value=330pF
C89 "GRM188Z71A475ME15D" 0603 2865,510 r90 bottom value=4.7uF
C90 "GRM155R70J104KA01D" 0402 3445,444.91 r270 bottom value=0.1uF
C91 "GRM155R70J104KA01D" 0402 3440,445 r270 top value=0.1uF
C92 "GRM1555C1E331JA01D" 0402S 3317.3,564.5 r0 top value=330pF
C93 "GRM1555C1E331JA01D" 0402S 3610.94,638.55 r0 top value=330pF
C94 "GRM1555C1E331JA01D" 0402S 3386.75,562.35 r180 top value=330pF
C95 "GRM1555C1E331JA01D" 0402S 3437.53,594.59 r90 top value=330pF
C96 "GRM1555C1E331JA01D" 0402S 3470.84,530.82 r0 top value=330pF
C97 "GRM1555C1E331JA01D" 0402S 3509.8,615.17 r90 top value=330pF
C98 "GRM155R70J104KA01D" 0402S 3344.98,1027.95 r180 bottom value=0.1uF
C99 "GRM155R71E104KE14D" 0402 5420,337.03 r180 bottom value=0.1uF
C100 "GRM155R71E104KE14D" 0402 4585,1002.06 r0 bottom value=0.1uF
C101 "GCM188R71C104KA37J" 0603 570.79,300.79 r180 top value=0.1uF
C102 "GRM32ER7YA106KA12K" 1210_270 330.45,344.68 r0 top value=10uF
C103 "GRM188R72A104KA35J" 0603 325.14,245.79 r0 top value=0.1uF
C104 "GRM32ER7YA106KA12K" 1210_270 476.85,90.35 r270 top value=10uF
C105 "GRM32ER7YA106KA12K" 1210_270 1400,685 r90 bottom value=10uF
C106 "GCM188R71C104KA37J" 0603 1429.67,694.07 r90 top value=0.1uF
C107 "GRM32ER7YA106KA12K" 1210_270 1605.65,685 r90 bottom value=10uF
C108 "GCM188R71C104KA37J" 0603 1626.91,694.07 r90 top value=0.1uF
C109 "GRM155R71C102KA01D" 0402 1621.58,560 r270 top value=1000pF
C110 "GCM188R71C104KA37J" 0603 890,343.54 r90 top value=0.1uF
C111 "GRM155R71E104KE14D" 0402 4859,842.82 r0 top value=0.1uF
C112 "GRM1555C1E120JA01D" 0402 6578.01,231.88 r270 bottom value=12pF
C113 "GRM1555C1E120JA01D" 0402 6578.01,339.12 r90 bottom value=12pF
C114 "GRM188Z71A106MA73D" 0603 6129,1193.28 r90 top value=10uF
C115 "GRM155R70J103KA01D" 0402 6194,1193.28 r90 top value=0.01uF
C116 "GRM155R70J105MA12D" 0402 6406.28,791.71 r90 top value=1uF
C117 "GRM155R70J104KA01D" 0402 6406.28,795.08 r90 bottom value=0.1uF
C118 "GRM155R70J105MA12D" 0402 6343.94,595.04 r0 top value=1uF
C119 "GRM155R70J104KA01D" 0402 6224.14,595.04 r180 top value=0.1uF
C120 "GRM155R70J105MA12D" 0402 6605.41,579.88 r180 top value=1uF
C121 "GRM155R70J104KA01D" 0402 6720.21,579.88 r0 bottom value=0.1uF
C122 "GRM188Z71A106MA73D" 0603 6060,853.65 r90 top value=10uF
C123 "GRM155R70J103KA01D" 0402 6130.09,837.15 r90 top value=0.01uF
C124 "GRM155R70J105MA12D" 0402 6605.41,520.83 r180 top value=1uF
C125 "GRM155R70J104KA01D" 0402 6720.21,520.83 r0 bottom value=0.1uF
C126 "GRM155R70J105MA12D" 0402 6605.41,638.94 r180 top value=1uF
C127 "GRM155R70J104KA01D" 0402 6720.21,638.94 r0 bottom value=0.1uF
C128 "GRM188Z71A106MA73D" 0603 6201.36,471.24 r180 bottom value=10uF
C129 "GRM155R70J103KA01D" 0402 6205.51,531.97 r180 bottom value=0.01uF
C130 "GRM155R70J105MA12D" 0402 6475,472.13 r90 top value=1uF
C131 "GRM155R70J104KA01D" 0402 6520,345 r270 bottom value=0.1uF
C132 "GRM155R70J105MA12D" 0402 6343.94,545.04 r0 top value=1uF
C133 "GRM155R70J104KA01D" 0402 6229.14,545.04 r180 top value=0.1uF
C134 "GRM155R71E104KE14D" 0402 1055.5,824.22 r180 bottom value=0.1uF
C135 "GRM155R71E103KA01D" 0402 205,1073.49 r270 bottom value=0.01uF
C136 "GRM155R71E104KE14D" 0402 1457.87,967.23 r180 top value=0.1uF
C137 "GRM155R71E104KE14D" 0402 1457.87,1190 r180 top value=0.1uF
C138 "GRM155R71E104KE14D" 0402 1457.87,1573.86 r180 top value=0.1uF
C139 "GRM155R71E104KE14D" 0402 1049.79,965.27 r0 top value=0.1uF
C140 "GRM155R71E104KE14D" 0402 1049.79,1190 r0 top value=0.1uF
C141 "GRM155R71E104KE14D" 0402 1036.93,1573.86 r0 top value=0.1uF
C142 "GRM155R71E104KE14D" 0402 1041.36,1404.93 r0 bottom value=0.1uF
C143 "GCM1555C1H8R0DA16D" 0402 1042.72,991.33 r90 bottom
C144 "GCM1555C1H8R0DA16D" 0402 1042.72,1106.13 r270 bottom
C145 "GRM155R71E104KE14D" 0402 345.31,1038.47 r0 top value=0.1uF
C146 "GCM155C71A105KE38D" 0402_070 827.49,875.32 r270 top value=1uF
C147 "GRM155R71E104KE14D" 0402 637.63,871.22 r90 top value=0.1uF
C148 "GCM155C71A105KE38D" 0402_070 700.81,1477.63 r90 top value=1uF
C149 "GRM155R71E103KA01D" 0402 1040.5,1197.99 r0 bottom value=0.01uF
C150 "GRM155R71E104KE14D" 0402 330.5,1355.66 r0 top value=0.1uF
C151 "GRM155R71E104KE14D" 0402 210.82,1193.78 r270 bottom value=0.1uF
C152 "GRM155R71E103KA01D" 0402 265.82,1193.78 r270 bottom value=0.01uF
C153 "GRM155C81C225KE11D" 0402 955,1071.57 r180 top value=2.2uF
C154 "GRM155R71E104KE14D" 0402 624.98,791.85 r180 bottom value=0.1uF
C155 "GRM155R71E104KE14D" 0402 624.98,791.85 r180 top value=0.1uF
C156 "GCM155C71A105KE38D" 0402_070 955,1120 r0 top value=1uF
C157 "GRM21BZ71A226ME15L" 0805_HV 2327.33,911.68 r180 top value=22uF
C158 "GRM21BZ71A226ME15L" 0805_HV 2327.33,1001.68 r180 top value=22uF
C159 "GRM32ER71A476ME15L" 1210_270 2310.42,976.68 r180 bottom value=47uF
C160 "GRM188R71E474KA12D" 0603 2262.84,651.68 r270 top value=0.47uF
C161 "GRM188Z71C475KE21D" 0603 5514.06,1077.1 r90 bottom value=4.7uF
C162 "GCM155C71A105KE38D" 0402_070 5485.58,1077.04 r90 top value=1uF
C163 "GRM155R71E104KE14D" 0402 5545.21,1072.1 r90 top value=0.1uF
C164 "GRM32ER7YA106KA12K" 1210_270 5854.13,1073.43 r90 top value=10uF
C165 "GRM155R70J104KA01D" 0402 5759.13,1072.1 r90 top value=0.1uF
C166 "GRM155R72A272KA01D" 0402 5704.25,978.43 r90 bottom value=2700pF
C167 "GRM32ER7YA106KA12K" 1210_270 2182.33,816.68 r90 top value=10uF
C168 "GRM32ER7YA106KA12K" 1210_270 2182.33,816.68 r90 bottom value=10uF
C169 "GRM21BZ71A226ME15L" 0805_HV 2689,1544.3 r180 top value=22uF
C170 "GRM21BZ71A226ME15L" 0805_HV 2689,1634.3 r180 top value=22uF
C171 "GRM32ER71A476ME15L" 1210_270 2672.09,1609.3 r180 bottom value=47uF
C172 "GRM188Z71C475KE21D" 0603 5514.13,1496.29 r90 bottom value=4.7uF
C173 "GCM155C71A105KE38D" 0402_070 5485.58,1493.07 r90 top value=1uF
C174 "GRM155R71E104KE14D" 0402 5545.21,1493.29 r90 top value=0.1uF
C175 "GRM32ER7YA106KA12K" 1210_270 5854.13,1492.62 r90 top value=10uF
C176 "GRM155R70J104KA01D" 0402 5759.13,1491.29 r90 top value=0.1uF
C177 "GRM188R71E474KA12D" 0603 2624.51,1284.3 r270 top value=0.47uF
C178 "GRM155R72A272KA01D" 0402 5704.25,1397.62 r90 bottom value=2700pF
C179 "GRM32ER7YA106KA12K" 1210_270 2544,1449.3 r90 bottom value=10uF
C180 "GRM32ER7YA106KA12K" 1210_270 2544,1449.3 r90 top value=10uF
C181 "GRM155R71E104KE14D" 0402 530.93,1915 r180 top value=0.1uF
C182 "GRM155R71E104KE14D" 0402 619.3,1835.87 r90 top value=0.1uF
C183 "GRM155R71E104KE14D" 0402 345.31,1815 r0 top value=0.1uF
C184 "GRM155R71E104KE14D" 0402 344.74,1865 r0 top value=0.1uF
C185 "GRM21BZ71A226ME15L" 0805_HV 2731.5,312.4 r180 top value=22uF
C186 "GRM155R71E104KE14D" 0402 2731.5,239.37 r180 top value=0.1uF
C187 "GCM155C71A105KE38D" 0402_070 2589.35,193.53 r90 top value=1uF
C188 "GRM155R71E104KE14D" 0402 2623.42,191.07 r90 top value=0.1uF
C189 "GRM1555C1E120JA01D" 0402 6391.38,1220 r180 bottom value=12pF
C190 "GRM1555C1E120JA01D" 0402 6498.62,1220 r0 bottom value=12pF
C191 "GRM188Z71A106MA73D" 0603 6129,1335.21 r90 top value=10uF
C192 "GRM155R70J103KA01D" 0402 6194,1331.38 r90 top value=0.01uF
C193 "GRM155R70J105MA12D" 0402 6406.28,1741.71 r90 top value=1uF
C194 "GRM155R70J104KA01D" 0402 6406.28,1745.08 r90 bottom value=0.1uF
C195 "GRM155R70J105MA12D" 0402 6348.94,1545.04 r0 top value=1uF
C196 "GRM155R70J104KA01D" 0402 6229.14,1545.04 r180 top value=0.1uF
C197 "GRM155R70J105MA12D" 0402 6601.41,1529.88 r180 top value=1uF
C198 "GRM155R70J104KA01D" 0402 6720.21,1529.88 r0 bottom value=0.1uF
C199 "GRM188Z71A106MA73D" 0603 6128.93,1006.97 r270 top value=10uF
C200 "GRM155R70J103KA01D" 0402 6184,1004.99 r270 top value=0.01uF
C201 "GRM155R70J105MA12D" 0402 6605.41,1470.83 r180 top value=1uF
C202 "GRM155R70J104KA01D" 0402 6720.21,1470.83 r0 bottom value=0.1uF
C203 "GRM155R70J105MA12D" 0402 6601.41,1588.94 r180 top value=1uF
C204 "GRM155R70J104KA01D" 0402 6720.21,1588.94 r0 bottom value=0.1uF
C205 "GRM188Z71A106MA73D" 0603 6201.36,1421.24 r180 bottom value=10uF
C206 "GRM155R70J103KA01D" 0402 6205.51,1481.97 r180 bottom value=0.01uF
C207 "GRM155R70J105MA12D" 0402 6475,1420.47 r90 top value=1uF
C208 "GRM155R70J104KA01D" 0402 6520,1295 r270 bottom value=0.1uF
C209 "GRM155R70J105MA12D" 0402 6348.94,1495.04 r0 top value=1uF
C210 "GRM155R70J104KA01D" 0402 6229.14,1495.04 r180 top value=0.1uF
C211 "GCM188R71H104KA57D" 0603 5730,80 r90 bottom value=0.1uF
C212 "GCM188R71H104KA57D" 0603 5730,330 r90 bottom value=0.1uF
C213 "GCM188R71H104KA57D" 0603 3740,1855 r270 bottom value=0.1uF
C214 "GCM1885C1H102JA16D" 0603 6049.18,80 r90 bottom value=1000pF
C215 "GRM1885C1H101JA01D" 0603 5974.18,80 r90 bottom value=100pF
C216 "GCM1885C1H102JA16D" 0603 5850,80 r90 bottom value=1000pF
C217 "GCM1885C1H102JA16D" 0603 6049.18,330 r90 bottom value=1000pF
C218 "GRM1885C1H101JA01D" 0603 5974.18,330 r90 bottom value=100pF
C219 "GCM1885C1H102JA16D" 0603 5850,330 r90 bottom value=1000pF
C220 "GCM1885C1H102JA16D" 0603 6342.17,140.82 r0 bottom value=1000pF
C221 "GCM1885C1H102JA16D" 0603 6047.13,344.67 r180 top value=1000pF
C222 "GCM155R71H472KA37D" 0402 6790,115 r90 top value=4700pF
C223 "GRM155R71E104KE14D" 0402 5333.66,-9.96 r90 bottom value=0.1uF
C224 "GCM188R71H104KA57D" 0603 5492.05,-56.53 r180 bottom value=0.1uF
C225 "GRM155R71E104KE14D" 0402 7032.8,-13.54 r270 bottom value=0.1uF
C226 "GRM155R71E104KE14D" 0402 6860,-89.6 r180 top value=0.1uF
C227 "GRM21BZ71E106KE15L" 0805_HV 135,874.79 r0 bottom value=10uF
C228 "GRM1555C1H150JA01D" 0402 508.65,974.76 r180 top value=15pF
C229 "GR442QR73D102KW01L" 1808 275.61,47.48 r180 top value=1000pF
C230 "GR442QR73D102KW01L" 1808 30.18,1384.48 r270 bottom value=1000pF
C231 "GRM155C81C225KE11D" 0402 202.83,812.27 r90 top value=2.2uF
C232 "GCM155C71A105KE38D" 0402_070 510,890.15 r90 top value=1uF
C233 "GRM155R71E104KE14D" 0402 427.56,812.27 r270 top value=0.1uF
C234 "GR442QR73D102KW01L" 1808 1248.86,875 r0 bottom value=1000pF
C235 "GR442QR73D102KW01L" 1808 7085,965 r0 top value=1000pF
C236 "C1608X7S1A335K080AC" 0603 2255.95,1263.5 r270 top value=3.3uF
C237 "GRM155R70J104KA01D" 0402 2195.94,1271.38 r270 top value=0.1uF
C238 "GRM155R71E104KE14D" 0402 5275,1028.69 r180 top value=0.1uF
C239 "GRM155R71E104KE14D" 0402 5189.88,614.77 r90 top value=0.1uF
C240 "GRM155R71E104KE14D" 0402 4520.38,1086.85 r90 top value=0.1uF
C241 "GRM155R71E104KE14D" 0402 4608.25,1438.99 r90 bottom value=0.1uF
C242 "GRM155R71E104KE14D" 0402 4886.38,1301.95 r180 top value=0.1uF
C243 "GRM155R71E104KE14D" 0402 4345.23,475.31 r90 bottom value=0.1uF
C244 "GRM155R71E104KE14D" 0402 4485,390.45 r270 bottom value=0.1uF
C245 "GRM155R71E104KE14D" 0402 4565,691.18 r270 top value=0.1uF
C246 "GRM155R71E104KE14D" 0402 4489.8,1565.98 r180 top value=0.1uF
C247 "GR442QR73D102KW01L" 1808 7035.15,1956.97 r0 top value=1000pF
C248 "GCM188R71C104KA37J" 0603 5914.09,548.38 r180 top value=0.1uF
C249 "GCM188R71C104KA37J" 0603 1006.86,275.41 r0 top value=0.1uF
C250 "GRM155R70J104KA01D" 0402 3409.37,900.9 r90 bottom value=0.1uF
C251 "GRM1555C1E331JA01D" 0402S 3491.62,321.22 r90 top value=330pF
C252 "GRM1555C1E331JA01D" 0402S 3377.4,508.89 r180 top value=330pF
C253 "GCM155C71A105KE38D" 0402_070 2363.56,461.96 r180 top value=1uF
C254 "GCM155C71A105KE38D" 0402_070 2271.19,450.13 r180 top value=1uF
D1 "SMBJ6.5CA" SMB-Bi 265.82,425.94 r270 bottom value=6.5V
D2 "150060VS75000" WL-SMCW_GREEN 1748.27,851.7 r270 top value=Green
D3 "150060VS75000" WL-SMCW_GREEN 113.02,1564.76 r0 top value=Green
D4 "150060VS75000" WL-SMCW_GREEN 2662.72,2062.24 r90 top value=Green
D5 "150060VS75000" WL-SMCW_GREEN 1886.27,-58.1 r270 top value=Green
D6 "150060VS75000" WL-SMCW_GREEN 2731.5,-26.84 r0 top value=Green
D7 "150060VS75000" WL-SMCW_GREEN 2519.29,2058.31 r90 top value=Green
D8 "150060VS75000" WL-SMCW_GREEN 2379.29,2058.31 r90 top value=Green
D9 "150060VS75000" WL-SMCW_GREEN 2239.29,2058.31 r90 top value=Green
D10 "150060VS75000" WL-SMCW_GREEN 2099.29,2058.31 r90 top value=Green
D11 "150060VS75000" WL-SMCW_GREEN 1927.87,2058.31 r90 top value=Green
D12 "150060VS75000" WL-SMCW_GREEN 1787.87,2058.31 r90 top value=Green
D13 "150060VS75000" WL-SMCW_GREEN 1647.87,2058.31 r90 top value=Green
D14 "150060VS75000" WL-SMCW_GREEN 1527.87,2058.31 r90 top value=Green
D15 "TPD1E01B04DPYR" DPY0002A 4163.5,315.32 r180 top
D16 "TPD1E01B04DPYR" DPY0002A 1847.72,335.1 r180 top
Designator10 "Comment" BRAKE_WAY_HOLES1X3 557.39,2189.63 r180 top
Designator10_1 "Comment" BRAKE_WAY_HOLES1X3 557.39,4848.63 r180 top
Designator10_1_1 "Comment" BRAKE_WAY_HOLES1X3 7022.59,-187.57 r0 top
Designator12 "Comment" BRAKE_WAY_HOLES1X3 116.59,2469.63 r0 top
Designator13 "Comment" BRAKE_WAY_HOLES1X3 2354.59,2469.63 r0 top
Designator14 "Comment" BRAKE_WAY_HOLES1X3 4592.59,2469.63 r0 top
Designator15 "Comment" BRAKE_WAY_HOLES1X3 7022.59,2469.63 r0 top
Designator23 "Comment" BRAKE_WAY_HOLES1X3 2846.06,2189.63 r180 top
Designator23_1 "Comment" BRAKE_WAY_HOLES1X3 2846.06,4848.63 r180 top
Designator23_1_1 "Comment" BRAKE_WAY_HOLES1X3 4592.59,-187.57 r0 top
Designator24 "Comment" BRAKE_WAY_HOLES1X3 4914.73,2189.63 r180 top
Designator24_1 "Comment" BRAKE_WAY_HOLES1X3 4914.73,4848.63 r180 top
Designator24_1_1 "Comment" BRAKE_WAY_HOLES1X3 2354.59,-187.57 r0 top
Designator25 "Comment" BRAKE_WAY_HOLES1X3 7283.39,2189.63 r180 top
Designator25_1 "Comment" BRAKE_WAY_HOLES1X3 7283.39,4848.63 r180 top
Designator25_1_1 "Comment" BRAKE_WAY_HOLES1X3 116.59,-187.57 r0 top
DS1 "150060RS75000" WL-SMCW_RED 2553,1842.4 r180 top value=Red
DS2 "150060RS75000" WL-SMCW_RED 5780.69,1940.86 r90 top value=Red
DS3 "150060RS75000" WL-SMCW_RED 113.02,1647.79 r0 top value=Red
FB1 "BLM18EG121SN1D" FP-BLM18EG121SN1D_0603-MFG 3850.08,414.71 r180 bottom
FB2 "BLM18EG121SN1D" FP-BLM18EG121SN1D_0603-MFG 3471.02,335 r180 bottom
FB3 "BLM18EG121SN1D" FP-BLM18EG121SN1D_0603-MFG 6038.68,1160.55 r0 top
FB4 "BLM18EG121SN1D" FP-BLM18EG121SN1D_0603-MFG 5965.92,820.9 r0 top
FB5 "BLM18EG121SN1D" FP-BLM18EG121SN1D_0603-MFG 6038.68,1299.44 r0 top
FB6 "BLM18EG121SN1D" FP-BLM18EG121SN1D_0603-MFG 6038.68,1038.64 r0 top
FID1 "Fiducial" Fiducial10-20 6845.38,2015 r90 top
FID2 "Fiducial" Fiducial10-20 142.29,1870.27 r90 top
FID3 "Fiducial" Fiducial10-20 965.86,-63.95 r90 top
FID4 "Fiducial" Fiducial10-20 6845.38,2015 r90 bottom
FID5 "Fiducial" Fiducial10-20 142.29,1870.27 r90 bottom
FID6 "Fiducial" Fiducial10-20 965.86,-63.95 r90 bottom
J1 "PBC02SAAN" Sullins_PBC02SAAN 1245.54,1825 r180 top locked
J1/J3 "SSQ-110-03-T-D" BOOSTERPACK_40PIN_J1J3 1904.17,150 r270 bottom locked
J2 "DM3BT-DSF-PEJS" Hirose_DM3BT-DSF-PEJS 920,212.52 r180 bottom
J2/J4 "SSQ-110-03-T-D" BoosterPack_40pin_J2J4 1904.17,1850 r270 bottom locked
J3 "PBC02SAAN" Sullins_PBC02SAAN 2525.62,-21.81 r270 top
J5 "2012670005" FP-2012670005_CONN_USB_9MM39_8MM21-MFG 5,350 r270 top
J5/J7 "SSQ-110-03-T-D" BOOSTERPACK_40PIN_J5J7 4404.17,150 r270 bottom locked
J6 "FH12A-40S-0.5SH(55)" FP-FH12A-40S-0.5SH(55)_FFC40-MFG 795.63,2050 r180 bottom locked
J6/J8 "SSQ-110-03-T-D" BoosterPack_40pin_J6J8 4404.17,1850 r270 bottom locked
J7 "LPJG16314A4NL" FP-LPJG16314A4NL_CONN_RJ45-MFG 7294,505 r90 top locked
J8 "LPJG16314A4NL" FP-LPJG16314A4NL_CONN_RJ45-MFG 7294,1495 r90 top locked
J9 "PBC02SAAN" Sullins_PBC02SAAN 1295,-13.95 r180 top
J10 "PBC02SAAN" Sullins_PBC02SAAN 1295,210 r0 top
J11 "PBC03SAAN" PBC03SAAN 5154.17,100 r180 top locked
J12 "PBC03SAAN" PBC03SAAN 5154.17,1900 r180 top locked
J13 "PBC02SAAN" Sullins_PBC02SAAN 5085.83,393.25 r0 top
J14 "PBC02SAAN" Sullins_PBC02SAAN 5217.11,393.25 r0 top
J15 "PBC02SAAN" Sullins_PBC02SAAN 6177.06,15 r180 top
J16 "PBC02SAAN" Sullins_PBC02SAAN 6177.06,265 r180 top
J17 "PBC02SAAN" Sullins_PBC02SAAN 1518.62,873.77 r90 top
J18 "PBC02SAAN" Sullins_PBC02SAAN 2545,484.47 r0 top
J23 "PRPC005DAAN-RC" Sullins_xxPC005DAAN-RC 3454.17,1850 r90 top locked
J24 "PEC05SAAN" Sullins_PxC05SAAN 5849.18,-35 r180 top locked
J25 "PEC05SAAN" Sullins_PxC05SAAN 5849.18,215 r180 top locked
J33 "OSTTE030161" On-Shore_OSTTE030161 6504.17,33.86 r0 top locked
J34 "1051640001" Molex_1051640001 -150,1072.19 r270 top locked
L1 "BLM21PG300SH1D" 0805_HV 331.85,168.85 r0 top value="30 ohm"
L2 "74438356022" WE-MAPI_4020 2495.75,850.74 r90 top value=2.2uH
L3 "74438356022" WE-MAPI_4020 2857.43,1483.36 r90 top value=2.2uH
L4 "74405020100" FP-74405020100_SMT_IND_2MM0_1MM6-MFG 2831.5,192.25 r90 top
LBL1 "THT-14-423-10" Label_650x200 6460,2037.06 r0 top
Logo1 "CE Mark" CE_Mark_5mm 585,1267.13 r0 top
Logo2 "Texas Instruments" TI_Stacked_Overlay_Small 4985,1628.31 r0 top locked
Logo3 "FCC disclaimer" FCC_disclaimer 9656.36,4210 r270 bottom
Logo4 "WEEE logo" WEEE_Minimum 5600,778.21 r180 bottom
Q1 "IRLML6401TRPBF" SOT-23 702.98,1757.76 r270 bottom value=-12V
Q2 "IRLML6401TRPBF" SOT-23 912.25,1867.02 r270 top value=-12V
